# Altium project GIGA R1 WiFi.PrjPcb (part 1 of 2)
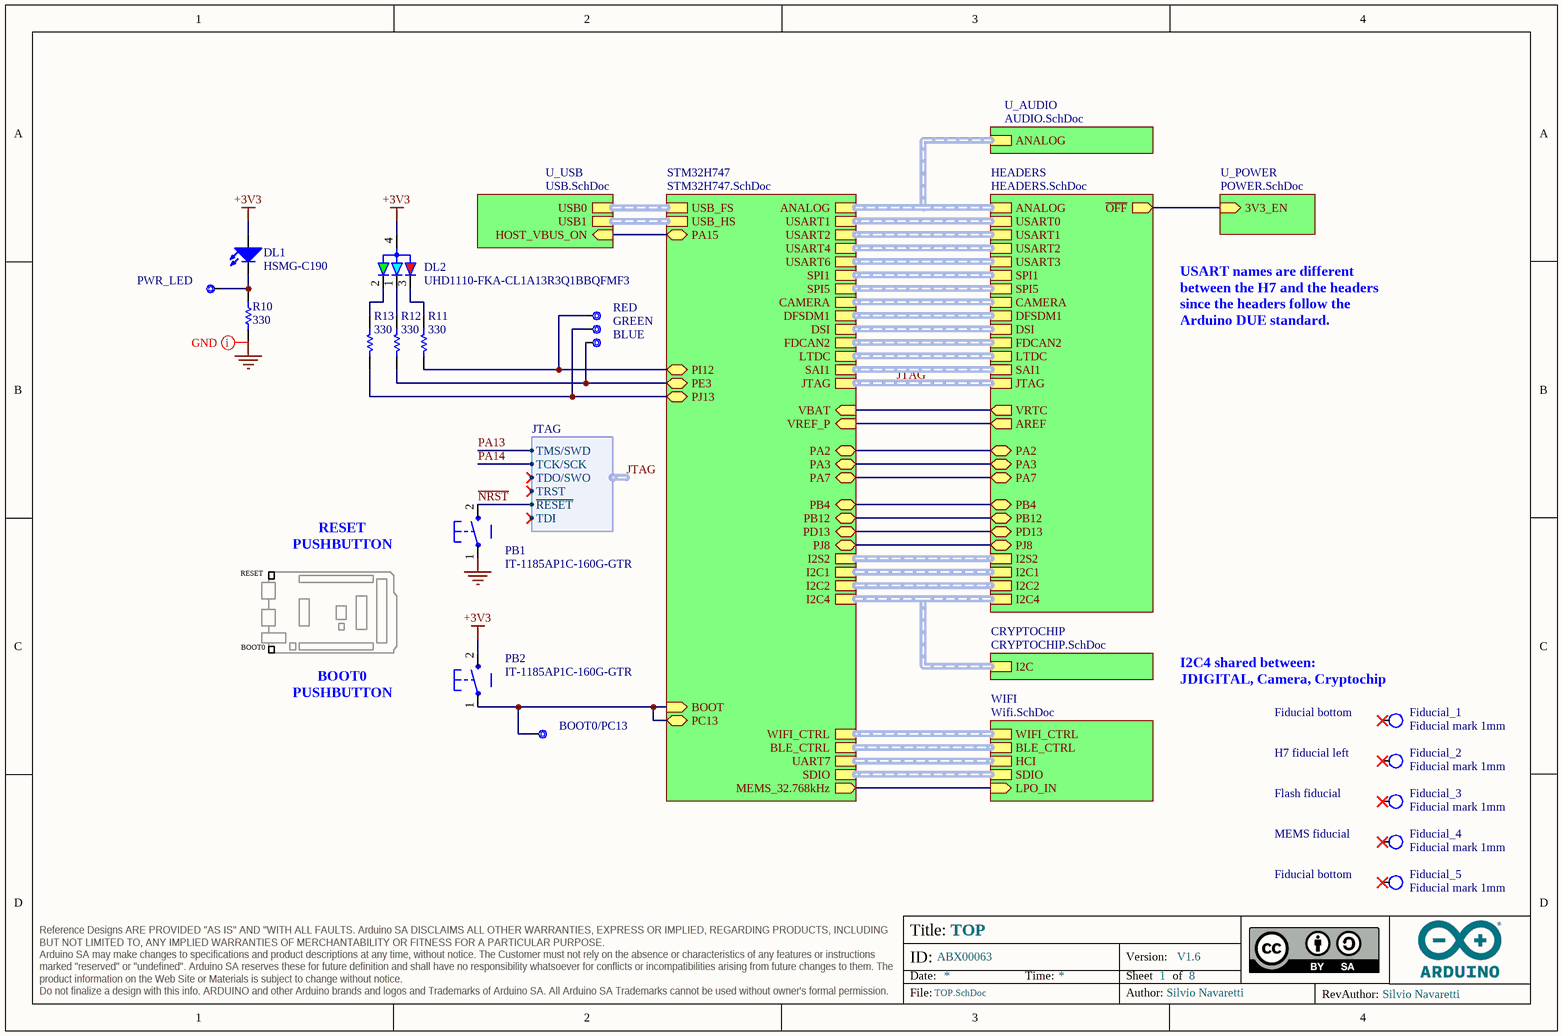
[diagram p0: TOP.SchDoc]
ADJUSTMENTS: _; BGA: X; BOARD_CODENAME: GIGA R1 WiFi; BOARD_INFO_AUTHOR: Silvio Navaretti; BOARD_INFO_AUTHOR_REV: Silvio Navaretti; DRILLS_BLIND: _; DRILLS_BURIED: _; DRILLS_COPPER_FILLING: _; DRILLS_FULL: X; DRILLS_LASER: _; DRILLS_PRESSFIT: _; DRILLS_RESIN_FILLING: _; DRILLS_SLOT: _; DRILLS_SOLDER_FILLING: X; EDGE_PLATING: _; ENIG: X; Er: _; FINISH_TBD: _; FLEX: _; FR4: X; FR4_HTG: _; HAL: _; HAL_LF: _; HOLE_TOP_BOTTOM: X; IPC1: _; IPC2: _; IPC3: _; IPCNA: _; MILLING: X; MIN_INSULATION_INNER: 0.127mm; MIN_INSULATION_OUTER: 0.127mm; MIN_TRACK_WIDTH_INNER: 0.127mm; MIN_TRACK_WIDTH_OUTER: 0.127mm; N_FIGURES: 6; NI/AU: _; NLAYERS: 6; PANEL_NO: _; PANEL_PROVIDED: X; PANEL_REQUESTED: _; PANEL_SIZE: 228mm x 179mm; PCB_SIZE: 101.6mm x 53.34mm; POLYMIDE: _; PRESSFIT: _; RIGID: X; RIGID/FLEX: _; SCORING: _; SILK_BOTTOM: X; SILK_COLOR: WHITE; SILK_TOP: X; SKU: ABX00063; SMD: X; SN/PB: _; SOLDERMASK_BOTTOM: X; SOLDERMASK_COLOR: BLUE; SOLDERMASK_PEELABLE_BOTTOM: _; SOLDERMASK_PEELABLE_COLOR: _; SOLDERMASK_PEELABLE_TOP: _; SOLDERMASK_TOP: X; TABS: _; TBD: _; THD: X; THICKNESS: 1.6mm; Version: V1.6
8 sheets, 228 parts. Net scope: hierarchical (ports join the sheet entries above them; power ports are global).
Board files: PCB.PcbDoc, PANEL.PcbDoc
Sheets:
  TOP.SchDoc
    U_AUDIO = AUDIO.SchDoc
    U_POWER = POWER.SchDoc
    U_USB = USB.SchDoc
    STM32H747 = STM32H747.SchDoc
    HEADERS = HEADERS.SchDoc
    WIFI = Wifi.SchDoc
    CRYPTOCHIP = CRYPTOCHIP.SchDoc

## Sheet TOP.SchDoc: TOP
size A4; Author: Silvio Navaretti; CompanyName: Arduino srl; DocumentNumber: ABX00063; Revision: V1.2; SheetNumber: 1; SheetTotal: 8; RevAuthor: Silvio Navaretti

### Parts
BLUE  CMP-018-0005-A.3  [TP-1.00MM]  (value not drawn)  (no BOM)
BOOT0/PC13  CMP-018-0005-A.3  [TP-1.00MM]  (value not drawn)  (no BOM)
DL1  HSMG-C190  [LEDC1608X80N-AK]
DL2  UHD1110-FKA-CL1A13R3Q1BBQFMF3  [UHD1110-FKA-CL1A13R3Q1BBQFMF3]
Fiducial_1  Fiducial mark 1mm  [Fiducial mark 1mm-Footprint-1]  (no BOM)
Fiducial_2  Fiducial mark 1mm  [Fiducial mark 1mm-Footprint-1]  (no BOM)
Fiducial_3  Fiducial mark 1mm  [Fiducial mark 1mm-Footprint-1]  (no BOM)
Fiducial_4  Fiducial mark 1mm  [Fiducial mark 1mm-Footprint-1]  (no BOM)
Fiducial_5  Fiducial mark 1mm  [Fiducial mark 1mm-Footprint-1]  (no BOM)
GREEN  CMP-018-0005-A.3  [TP-1.00MM]  (value not drawn)  (no BOM)
PB1  IT-1185AP1C-160G-GTR  [C&K_PTS820_NO_HOLES-1]
PB2  IT-1185AP1C-160G-GTR  [C&K_PTS820_NO_HOLES-1]
PWR_LED  CMP-018-0005-A.3  [TP-1.00MM]  (value not drawn)  (no BOM)
R10  value 330  [RES-0402]  (hidden comment: CRCW0402330RJNED)
R11  value 330  [RES-0402]  (hidden comment: CRCW0402330RJNED)
R12  value 330  [RES-0402]  (hidden comment: CRCW0402330RJNED)
R13  value 330  [RES-0402]  (hidden comment: CRCW0402330RJNED)
RED  CMP-018-0005-A.3  [TP-1.00MM]  (value not drawn)  (no BOM)

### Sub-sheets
CRYPTOCHIP = CRYPTOCHIP.SchDoc: I2C (harness I2C)
HEADERS = HEADERS.SchDoc: SPI5 (harness SPI), PB4 (bidir), I2C1 (harness I2C), LTDC (harness LTDC), SAI1 (harness SAI), I2C4 (harness I2C), USART0 (harness UART), USART3 (harness UART), USART2 (harness UART), USART1 (harness UART), I2C2 (harness I2C), PD13 (bidir), PA7 (bidir), PJ8 (bidir), PA2 (bidir), PA3 (bidir), ANALOG (harness ANALOG), FDCAN2 (harness FDCAN), I2S2 (harness I2S), DSI (harness DISPLAY), DFSDM1 (harness DFSDM), SPI1 (harness SPI), CAMERA (harness ARDUCAM), AREF (out), ~{OFF} (out), VRTC (out), JTAG (harness JTAG), PB12 (bidir)
STM32H747 = STM32H747.SchDoc: BOOT (in), DSI (harness DISPLAY), VREF_P (in), SDIO (harness SDC), USB_FS (harness USB), USB_HS (harness USB), PI12 (bidir), PE3 (bidir), PJ13 (bidir), UART7 (harness UART), PC13 (bidir), I2C1 (harness I2C), USART1 (harness UART), USART6 (harness UART), USART4 (harness UART), USART2 (harness UART), I2C2 (harness I2C), ANALOG (harness ANALOG), FDCAN2 (harness FDCAN), LTDC (harness LTDC), SAI1 (harness SAI), I2S2 (harness I2S), DFSDM1 (harness DFSDM), I2C4 (harness I2C), CAMERA (harness ARDUCAM), SPI5 (harness SPI), SPI1 (harness SPI), BLE_CTRL (harness BLE CTRL), WIFI_CTRL (harness WiFi CTRL), PD13 (bidir), PB4 (bidir), PA7 (bidir), PJ8 (bidir), PA2 (bidir), PA3 (bidir), JTAG (harness JTAG), PB12 (bidir), VBAT (in), MEMS_32.768kHz (out), PA15 (bidir)
U_AUDIO = AUDIO.SchDoc: ANALOG (harness ANALOG)
U_POWER = POWER.SchDoc: 3V3_EN (in)
U_USB = USB.SchDoc: USB0 (harness USB), USB1 (harness USB), HOST_VBUS_ON (in)
WIFI = Wifi.SchDoc: BLE_CTRL (harness BLE CTRL), HCI (harness UART), WIFI_CTRL (harness WiFi CTRL), SDIO (harness SDC), LPO_IN (in)

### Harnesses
JTAG: ~{RESET}, TCK/SCK, TDI, TDO/SWO, TMS/SWD, TRST

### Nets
+3V3: DL1.A DL2.4(ANODE) PB2.2
GND: PB1.1 R10.1
MEMS_32.768kHz: sheet STM32H747/MEMS_32.768kHz, sheet WIFI/LPO_IN
~{NRST}: PB1.2 ; sheet STM32H747/JTAG.~{RESET}  [project net JTAG.~{RESET}]
PA2: sheet STM32H747/PA2, sheet HEADERS/PA2
PA3: sheet STM32H747/PA3, sheet HEADERS/PA3
PA7: sheet STM32H747/PA7, sheet HEADERS/PA7
PA15: sheet U_USB/HOST_VBUS_ON, sheet STM32H747/PA15
PB4: sheet STM32H747/PB4, sheet HEADERS/PB4
PB12: sheet STM32H747/PB12, sheet HEADERS/PB12
PC13: BOOT0/PC13.X PB2.1 ; sheet STM32H747/BOOT, sheet STM32H747/PC13
PD13: sheet STM32H747/PD13, sheet HEADERS/PD13
PE3: BLUE.X R12.2 ; sheet STM32H747/PE3
PI12: R11.2 RED.X ; sheet STM32H747/PI12
PJ8: sheet STM32H747/PJ8, sheet HEADERS/PJ8
PJ13: GREEN.X R13.2 ; sheet STM32H747/PJ13
Net3V3_EN_X: sheet U_POWER/3V3_EN, sheet HEADERS/~{OFF}
NetDL1_C: DL1.C PWR_LED.X R10.2
NetDL2_1: DL2.1(BLUE_C) R12.1
NetDL2_2: DL2.2(GREEN_C) R13.1
NetDL2_3: DL2.3(RED_C) R11.1
NetJ1_3: sheet STM32H747/VBAT, sheet HEADERS/VRTC
NetJDIGITAL_3: sheet STM32H747/VREF_P, sheet HEADERS/AREF

Not connected (* = marked no-connect by the designer): Fiducial_1 1*; Fiducial_2 1*; Fiducial_3 1*; Fiducial_4 1*; Fiducial_5 1*

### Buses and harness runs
harness JTAG = sheet HEADERS/JTAG = sheet STM32H747/JTAG
harness sheet CRYPTOCHIP/I2C = sheet HEADERS/I2C4 = sheet STM32H747/I2C4
harness sheet HEADERS/ANALOG = sheet STM32H747/ANALOG = sheet U_AUDIO/ANALOG
harness sheet HEADERS/CAMERA = sheet STM32H747/CAMERA
harness sheet HEADERS/DFSDM1 = sheet STM32H747/DFSDM1
harness sheet HEADERS/DSI = sheet STM32H747/DSI
harness sheet HEADERS/FDCAN2 = sheet STM32H747/FDCAN2
harness sheet HEADERS/I2C1 = sheet STM32H747/I2C1
harness sheet HEADERS/I2C2 = sheet STM32H747/I2C2
harness sheet HEADERS/I2S2 = sheet STM32H747/I2S2
harness sheet HEADERS/LTDC = sheet STM32H747/LTDC
harness sheet HEADERS/SAI1 = sheet STM32H747/SAI1
harness sheet HEADERS/SPI1 = sheet STM32H747/SPI1
harness sheet HEADERS/SPI5 = sheet STM32H747/SPI5
harness sheet HEADERS/USART0 = sheet STM32H747/USART1
harness sheet HEADERS/USART1 = sheet STM32H747/USART2
harness sheet HEADERS/USART2 = sheet STM32H747/USART4
harness sheet HEADERS/USART3 = sheet STM32H747/USART6
harness sheet STM32H747/BLE_CTRL = sheet WIFI/BLE_CTRL
harness sheet STM32H747/SDIO = sheet WIFI/SDIO
harness sheet STM32H747/UART7 = sheet WIFI/HCI
harness sheet STM32H747/USB_FS = sheet U_USB/USB0
harness sheet STM32H747/USB_HS = sheet U_USB/USB1
harness sheet STM32H747/WIFI_CTRL = sheet WIFI/WIFI_CTRL

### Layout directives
net class GND: GND

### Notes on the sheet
- USART names are different between the H7 and the headers since the headers follow the Arduino DUE standard.
- RESET
- RESET
  PUSHBUTTON
- BOOT0
- BOOT0
  PUSHBUTTON
- (near Fiducial_1) I2C4 shared between:
  JDIGITAL, Camera, Cryptochip
- (near Fiducial_1) Fiducial bottom
- (near Fiducial_2) H7 fiducial left
- Flash fiducial
- MEMS fiducial
- Fiducial bottom

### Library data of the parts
BLUE BOOT0/PC13 GREEN PWR_LED RED = UT0013-A.4: Test point 1.00mm
DL1 = L0009-A.5: LED SMD 0603 GREEN/568 15mcd 120^; Manufacturer: Broadcom; Code Arduino: 2204
DL2 = L0026-A.4: LED RGB BLACK BODY SMD; Manufacturer: Cree LED; Code Arduino: L0026
Fiducial_1-Fiducial_5 = UT0023-A.6: Fiducial mark 1mm clearance 2mm
PB1 PB2 = B0001-A.7: PUSHBUTTON WHITE NO ANCHORS; Manufacturer: Switronic; Code Arduino: 0173
R10-R13 = R0017-A.23: RES CHIP 0402 330R 5% 1/16W; Manufacturer: Vishay; Power: 62.5mW; Code Arduino: 2229; Temperature coefficient: 200ppm

## Sheet AUDIO.SchDoc: AUDIO
size A4; Author: Silvio Navaretti; CompanyName: Arduino srl; DocumentNumber: ABX00063; Revision: V1.4; SheetNumber: 7; SheetTotal: 8; RevAuthor: Silvio Navaretti
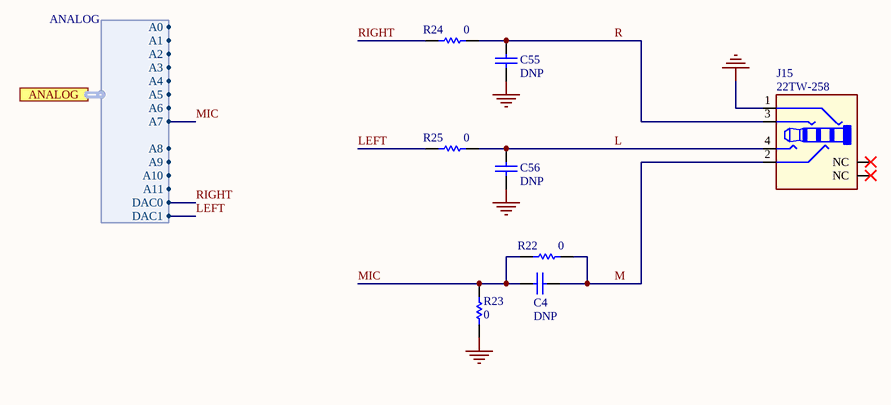
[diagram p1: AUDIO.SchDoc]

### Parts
C4  DNP CAP 0402  [CAP-0402]  (value not drawn)
C55  DNP CAP 0402  [CAP-0402]  (value not drawn)
C56  DNP CAP 0402  [CAP-0402]  (value not drawn)
J15  22TW-258  [22TW-258-Footprint-1]
R22  value 0  [RES-0402]  (hidden comment: CRCW04020000Z0EDC)
R23  value 0  [RES-0402]  (hidden comment: CRCW04020000Z0EDC)
R24  value 0  [RES-0402]  (hidden comment: CRCW04020000Z0EDC)
R25  value 0  [RES-0402]  (hidden comment: CRCW04020000Z0EDC)

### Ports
ANALOG (harness ANALOG)

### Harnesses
ANALOG: A0, A1, A2, A3, A7, A6, A5, A4, A8, A9, A10, A11, DAC0, DAC1

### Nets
GND: C55.1 C56.1 J15.1 R23.1
L: C56.2 J15.4 R25.2  [project net L_7]
LEFT: R25.1 ; port ANALOG.DAC1
M: C4.1 J15.2 R22.2  [project net M_7]
MIC: C4.2 R22.1 R23.2 ; port ANALOG.A7
R: C55.2 J15.3 R24.2  [project net R_7]
RIGHT: R24.1 ; port ANALOG.DAC0  [project net PA4]

Not connected (* = marked no-connect by the designer): J15 NC1(NC)* NC2(NC)*

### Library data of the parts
C4 C55 C56 = C0095-A.6: Code Arduino: C0095
J15 = J0273-A.8: Conn Jack 4 POLES 3.5mm SMD; Manufacturer: 4UCONN; Code Arduino: J0273
R22-R25 = R0000-A.23: RES CHIP 0402 0R 1/16W; Manufacturer: Vishay; Power: 62.5mW; Tolerance: 0%; Code Arduino: 0039; Temperature coefficient: 0ppm

## Sheet POWER.SchDoc: POWER
size A4; Author: Silvio Navaretti; CompanyName: Arduino srl; DocumentNumber: ABX00063; Revision: V1.4; SheetNumber: 4; SheetTotal: 8; RevAuthor: Silvio Navaretti
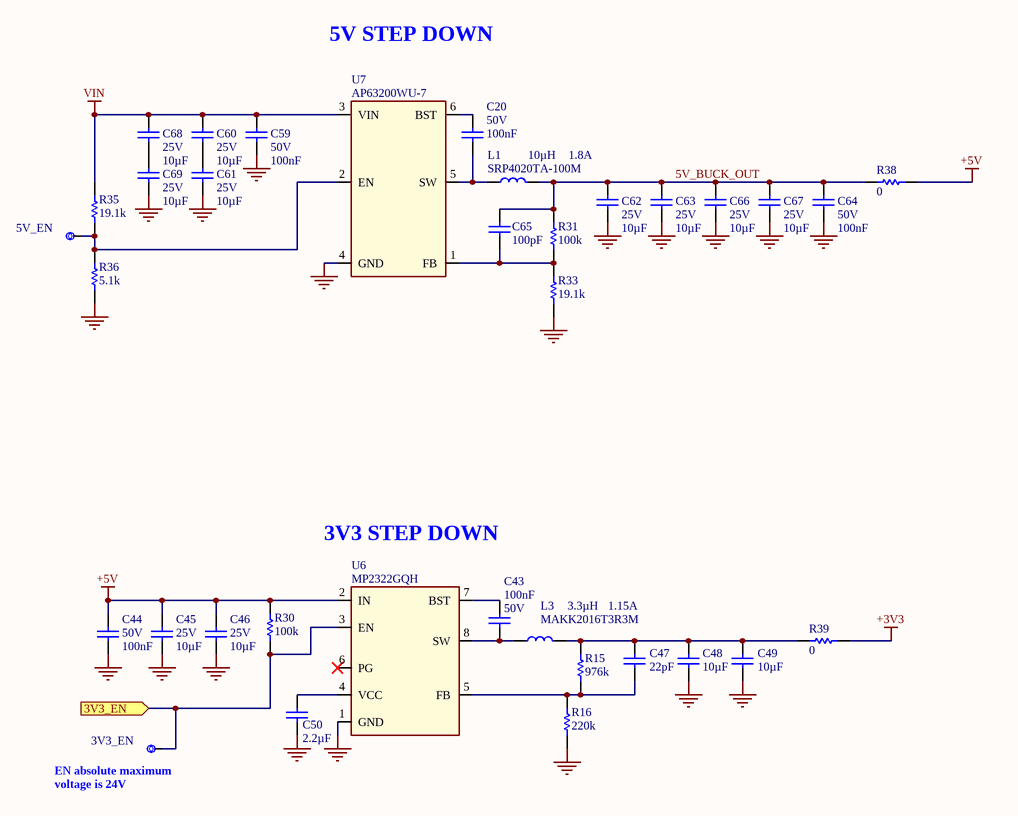
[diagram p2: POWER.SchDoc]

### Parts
3V3_EN  CMP-018-0005-A.3  [TP-1.00MM]  (value not drawn)  (no BOM)
5V_EN  CMP-018-0005-A.3  [TP-1.00MM]  (value not drawn)  (no BOM)
C20  value 100nF  Voltage: 50V  [CAP-0402]  (hidden comment: GRM155R61H104KE19D)
C43  value 100nF  Voltage: 50V  [CAP-0402]  (hidden comment: GRM155R61H104KE19D)
C44  value 100nF  Voltage: 50V  [CAP-0402]  (hidden comment: GRM155R61H104KE19D)
C45  value 10µF  Voltage: 25V  [CAP-0603]  (hidden comment: C1608A106M250NT)
C46  value 10µF  Voltage: 25V  [CAP-0603]  (hidden comment: C1608A106M250NT)
C47  value 22pF  [CAP-0402]  (hidden comment: 0402N220J500CT)
C48  value 10µF  [CAP-0603]  (hidden comment: C1608A106M250NT)
C49  value 10µF  [CAP-0603]  (hidden comment: C1608A106M250NT)
C50  value 2.2µF  [CAP-0402]  (hidden comment: GRM155R60J225KE95D)
C59  value 100nF  Voltage: 50V  [CAP-0402]  (hidden comment: GRM155R61H104KE19D)
C60  value 10µF  Voltage: 25V  [CAP-0603]  (hidden comment: C1608A106M250NT)
C61  value 10µF  Voltage: 25V  [CAP-0603]  (hidden comment: C1608A106M250NT)
C62  value 10µF  Voltage: 25V  [CAP-0603]  (hidden comment: C1608A106M250NT)
C63  value 10µF  Voltage: 25V  [CAP-0603]  (hidden comment: C1608A106M250NT)
C64  value 100nF  Voltage: 50V  [CAP-0402]  (hidden comment: GRM155R61H104KE19D)
C65  value 100pF  [CAP-0402]  (hidden comment: CC0402JRNPO9BN101)
C66  value 10µF  Voltage: 25V  [CAP-0603]  (hidden comment: C1608A106M250NT)
C67  value 10µF  Voltage: 25V  [CAP-0603]  (hidden comment: C1608A106M250NT)
C68  value 10µF  Voltage: 25V  [CAP-0603]  (hidden comment: C1608A106M250NT)
C69  value 10µF  Voltage: 25V  [CAP-0603]  (hidden comment: C1608A106M250NT)
L1  SRP4020TA-100M  Inductance: 10µH  Current: 1.8A  [SRP4020]
L3  MAKK2016T3R3M  Max DC Current: 1.15A  Inductance: 3.3µH  [MAKK2016T3R3M-Footprint-1]
R15  value 976k  [RES-0402]  (hidden comment: CRCW0402976KFKED)
R16  value 220k  [RES-0402]  (hidden comment: CRCW0402220KFKED)
R30  value 100k  [RES-0402]  (hidden comment: CRCW0402100KFKEDC)
R31  value 100k  [RES-0402]  (hidden comment: CRCW0402100KFKEDC)
R33  value 19.1k  [RES-0402]  (hidden comment: CRCW040219K1FKEDC)
R35  value 19.1k  [RES-0402]  (hidden comment: CRCW040219K1FKEDC)
R36  value 5.1k  [RES-0402]  (hidden comment: RC0402FR-075K1L)
R38  value 0  [RES-0402]  (hidden comment: CRCW04020000Z0EDC)
R39  value 0  [RES-0402]  (hidden comment: CRCW04020000Z0EDC)
U6  MP2322GQH  [QFN50P150X200X90-8L]
U7  AP63200WU-7  [SOT95P280X100-6N]

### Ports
3V3_EN (in)

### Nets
+3V3: R39.2
+5V: C44.1 C45.2 C46.2 R30.1 R38.2 U6.2(IN)
GND: C44.2 C45.1 C46.1 C48.1 C49.1 C50.1 C59.2 C61.1 C62.1 C63.1 C64.2 C66.1 C67.1 C69.1 R16.1 R33.1 R36.2 U6.1(GND) U7.4(GND)
VIN: C59.1 C60.2 C68.2 R35.1 U7.3(VIN)
5V_BUCK_OUT: C62.2 C63.2 C64.1 C65.2 C66.2 C67.2 L1.2 R31.1 R38.1  [project net 5V_BUCK_OUT_4]
Net3V3_EN_X: 3V3_EN.X R30.2 U6.3(EN) ; port 3V3_EN
Net5V_EN_X: 5V_EN.X R35.2 R36.1 U7.2(EN)
NetC20_1: C20.1 U7.6(BST)
NetC20_2: C20.2 L1.1 U7.5(SW)
NetC43_1: C43.1 L3.1 U6.8(SW)
NetC43_2: C43.2 U6.7(BST)
NetC47_1: C47.1 R15.1 R16.2 U6.5(FB)
NetC47_2: C47.2 C48.2 C49.2 L3.2 R15.2 R39.1
NetC50_2: C50.2 U6.4(VCC)
NetC60_1: C60.1 C61.2
NetC65_1: C65.1 R31.2 R33.2 U7.1(FB)
NetC68_1: C68.1 C69.2

Not connected (* = marked no-connect by the designer): U6 6(PG)*

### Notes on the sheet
- 5V STEP DOWN
- 3V3 STEP DOWN
- (near 3V3_EN) EN absolute maximum voltage is 24V

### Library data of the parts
3V3_EN 5V_EN = UT0013-A.4: Test point 1.00mm
C20 C43 C44 C59 C64 = C0015-A.14: CAP CHIP 0402 100nF 10% 50V X5R; Manufacturer: Murata; Code Arduino: A5141
C45 C46 C48 C49 C60-C63 C66-C69 = C0047-A.18: CAP CHIP 0603 10uF 20% 25V X5R; Manufacturer: Hottech; Code Arduino: 2213
C47 = C0029-A.14: CAP CHIP 0402 22pF 5% 50V C0G; Manufacturer: Walsin; Code Arduino: 0137
C50 = C0031-A.14: CAP CHIP 0402 2.2uF 10% 6.3V X5R; Manufacturer: Murata; Code Arduino: A5529
C65 = C0013-A.4: CAP CHIP 0402 100pF 10% 50V C0G; Manufacturer: Yageo; Code Arduino: C0013; Tolerance: 5%
L1 = I0065-A.2: IND FIXED 10UH IRMS 1.8A ISAT 2.3A 243m ohm SMD 4.45x4mm; Manufacturer: Bourns; Value: 10u; Code Arduino: I0065
L3 = I0045-A.10: IND CHIP 0806 3.3 uH 20% 1.2A; Manufacturer: Taiyo Yuden; Core Material: Metal; DC Resistance (DCR): 255mR; Code Arduino: I0045; Test Frequency: 2MHz; Shielding: Shielded; Value: 3.3µH
R15 = R0070-A.24: RES CHIP 0402 976k 1% 1/16W; Manufacturer: Vishay; Power: 62.5mW; Code Arduino: R0070; Temperature coefficient: 100ppm
R16 = R0028-A.23: RES CHIP 0402 220k 1% 1/16W; Manufacturer: Vishay; Code Arduino: 2334; Power: 62.5mW; Temperature coefficient: 200ppm
R30 R31 = R0001-A.23: RES CHIP 0402 100k 1% 1/16W; Manufacturer: Vishay; Power: 62.5mW; Code Arduino: 0134; Temperature coefficient: 100ppm
R33 = R0033-A.23: RES CHIP 0402 19k1 1% 1/16W; Manufacturer: Vishay; Code Arduino: A5369; Power: 62.5mW; Temperature coefficient: 100ppm
R35 = R0033-A.23: RES CHIP 0402 19k1 1% 1/16W; Manufacturer: Vishay; Power: 62.5mW; Code Arduino: A5369; Temperature coefficient: 100ppm
R36 = R0210-A.18: RES CHIP 0402 5k1 1% 1/16W; Manufacturer: YAGEO; Power: 63mW; Code Arduino: R0210; Temperature coefficient: 100ppm
R38 R39 = R0000-A.23: as R22 on sheet AUDIO
U6 = U0072-A.8: IC STEP DOWN CONV 1A 22V QFN8; Manufacturer: Monolithic Power Systems; Code Arduino: U0072
U7 = U0241-A.6: IC BUCK VIN 3V8 to 32V Iout 4A duty 100% fsw 500kHz TSOT26; Manufacturer: Diodes Incorporated; Code Arduino: U0241

## Sheet USB.SchDoc: USB
size A4; Author: Silvio Navaretti; CompanyName: Arduino srl; DocumentNumber: ABX00063; Revision: V1.4; SheetNumber: 3; SheetTotal: 8; RevAuthor: Silvio Navaretti
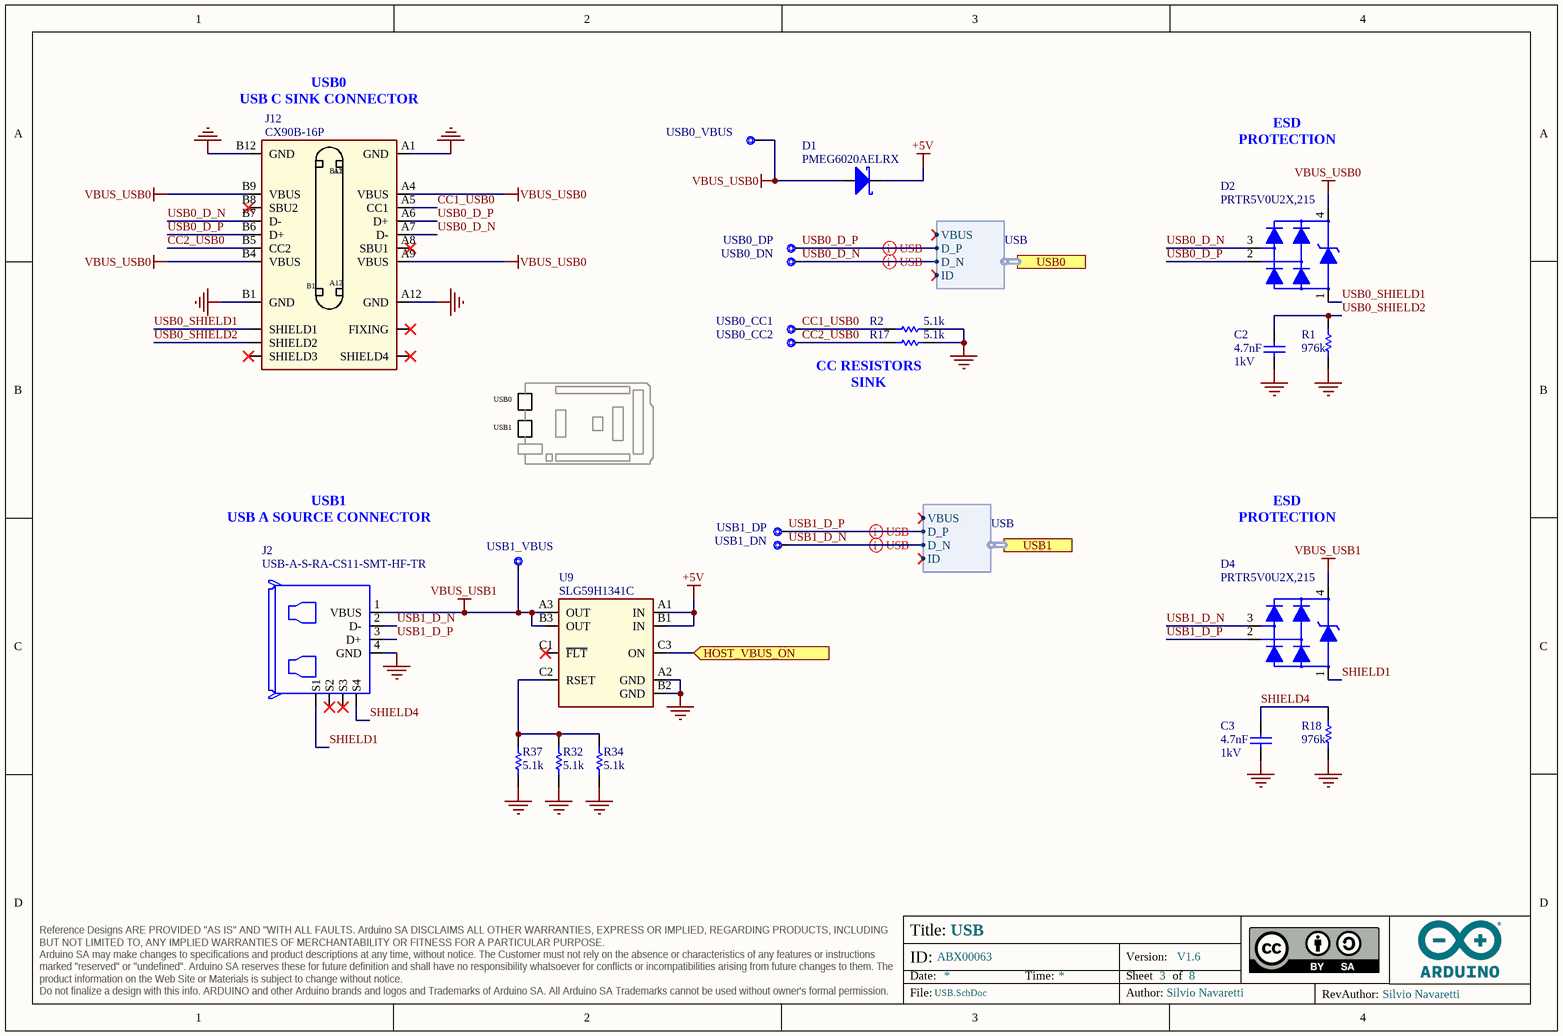
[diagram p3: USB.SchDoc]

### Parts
C2  value 4.7nF  Voltage: 1kV  [CAP-0805]  (hidden comment: FV21X472K102ECG)
C3  value 4.7nF  Voltage: 1kV  [CAP-0805]  (hidden comment: FV21X472K102ECG)
D1  PMEG6020AELRX  [SOD123-1]
D2  PRTR5V0U2X,215  [SOT190P230X110-4N]
D4  PRTR5V0U2X,215  [SOT190P230X110-4N]
J2  USB-A-S-RA-CS11-SMT-HF-TR  [USB-A-S-RA-CS11-SMT-HF-TR]
J12  CX90B-16P  [CX90B-16P-Footprint-1]
R1  value 976k  [RES-0402]  (hidden comment: CRCW0402976KFKED)
R2  value 5.1k  [RES-0402]  (hidden comment: RC0402FR-075K1L)
R17  value 5.1k  [RES-0402]  (hidden comment: RC0402FR-075K1L)
R18  value 976k  [RES-0402]  (hidden comment: CRCW0402976KFKED)
R32  value 5.1k  [RES-0402]  (hidden comment: RC0402FR-075K1L)
R34  value 5.1k  [RES-0402]  (hidden comment: RC0402FR-075K1L)
R37  value 5.1k  [RES-0402]  (hidden comment: RC0402FR-075K1L)
U9  SLG59H1341C  [BGA9C40P3X3_121X121X62]
USB0_CC1  CMP-018-0005-A.3  [TP-1.00MM]  (value not drawn)  (no BOM)
USB0_CC2  CMP-018-0005-A.3  [TP-1.00MM]  (value not drawn)  (no BOM)
USB0_DN  CMP-018-0005-A.3  [TP-1.00MM]  (value not drawn)  (no BOM)
USB0_DP  CMP-018-0005-A.3  [TP-1.00MM]  (value not drawn)  (no BOM)
USB0_VBUS  CMP-018-0005-A.3  [TP-1.00MM]  (value not drawn)  (no BOM)
USB1_DN  CMP-018-0005-A.3  [TP-1.00MM]  (value not drawn)  (no BOM)
USB1_DP  CMP-018-0005-A.3  [TP-1.00MM]  (value not drawn)  (no BOM)
USB1_VBUS  CMP-018-0005-A.3  [TP-1.00MM]  (value not drawn)  (no BOM)

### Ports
HOST_VBUS_ON (in), USB0 (harness USB), USB1 (harness USB)

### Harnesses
USB: VBUS, D_P, D_N, ID

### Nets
+5V: D1.C U9.A1(IN) U9.B1(IN)
GND: C2.1 C3.1 J2.4(GND) J12.A1(GND) J12.A12(GND) J12.B1(GND) J12.B12(GND) R1.1 R2.2 R17.2 R18.1 R32.1 R34.1 R37.1 U9.A2(GND) U9.B2(GND)
VBUS_USB0: D1.A D2.4 J12.A4(VBUS) J12.A9(VBUS) J12.B4(VBUS) J12.B9(VBUS) USB0_VBUS.X
VBUS_USB1: D4.4 J2.1(VBUS) U9.A3(OUT) U9.B3(OUT) USB1_VBUS.X
CC1_USB0: J12.A5(CC1) R2.1 USB0_CC1.X  [project net CC1_USB0_3]
CC2_USB0: J12.B5(CC2) R17.1 USB0_CC2.X  [project net CC2_USB0_3]
PA15: U9.C3(ON) ; port HOST_VBUS_ON
SHIELD1: D4.1 J2.SHIELD1(S1)  [project net SHIELD1_3]
SHIELD4: C3.2 J2.SHIELD4(S4) R18.2  [project net SHIELD4_3]
USB0_D_N: D2.3 J12.A7(D-) J12.B7(D-) USB0_DN.X ; port USB0.D_N
USB0_D_P: D2.2 J12.A6(D+) J12.B6(D+) USB0_DP.X ; port USB0.D_P
USB0_SHIELD1: D2.1 J12.SHIELD1  [project net USB0_SHIELD1_3]
USB0_SHIELD2: C2.2 J12.SHIELD2 R1.2  [project net USB0_SHIELD2_3]
USB1_D_N: D4.3 J2.2(D-) USB1_DN.X ; port USB1.D_N
USB1_D_P: D4.2 J2.3(D+) USB1_DP.X ; port USB1.D_P
NetR32_2: R32.2 R34.2 R37.2 U9.C2(RSET)

Not connected (* = marked no-connect by the designer): J2 SHIELD2(S2)* SHIELD3(S3)*; J12 A8(SBU1)* B8(SBU2)* FIXING* SHIELD3* SHIELD4*; U9 C1(~{FLT})*

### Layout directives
differential pair; differential pair class USB: USB0_D_N, USB0_D_P, USB1_D_N, USB1_D_P

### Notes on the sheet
- (near J12) USB0
  USB C SINK CONNECTOR
- ESD PROTECTION
- USB0
- USB1
- CC RESISTORS
  SINK
- USB1
  USB A SOURCE CONNECTOR

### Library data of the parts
C2 C3 = C0059-A.14: CAP CHIP 0805 4.7nF 10% 1000V X7R; Manufacturer: PSA Shenzen; Code Arduino: 0689
D1 = D0026-A.6: DIODE SCHOTTKY SMD 2A 60V SOD123FL; Manufacturer: Nexperia; Manucturer Part Number 2: SS26L; Code Arduino: 2208; Forward Voltage: 0.6V; Manucturer 2: Hottech
D2 D4 = D0025-A.5: TVS ARRAY 4LIN.8kV 1pF SOT143B; Manufacturer: Nexperia; Device Type: ESD protection; Code Arduino: 2209
J2 = J0329-A.9: CONN USB A 2.0 FEMALE RIGHT ANGLE SMD + TH TAPE AND REEL; Manufacturer: Adam Tech; Code Arduino: J0329
J12 = J0272-A.3: CONN RCPT USB3.1 TYPEC 16POS SMD; Manufacturer: Hirose; Code Arduino: J0272
R1 R18 = R0070-A.24: as R15 on sheet POWER
R2 R17 R32 R34 R37 = R0210-A.18: RES CHIP 0402 5k1 1% 1/16W; Manufacturer: YAGEO; Code Arduino: R0210; Power: 63mW; Temperature coefficient: 100ppm
U9 = U0272-A.3: IC Power switch 2.5V to 5.5V 1A reverse blocking, adj current limit, WLCSP9; Manufacturer: Renesas; Code Arduino: U0272
USB0_CC1 USB0_CC2 USB0_DN USB0_DP USB0_VBUS USB1_DN USB1_DP USB1_VBUS = UT0013-A.4: Test point 1.00mm

## Sheet STM32H747.SchDoc: STM32H747
size A3; Author: Silvio Navaretti; CompanyName: Arduino srl; DocumentNumber: ABX00063; Revision: V1.4; SheetNumber: 5; SheetTotal: 8; RevAuthor: Silvio Navaretti
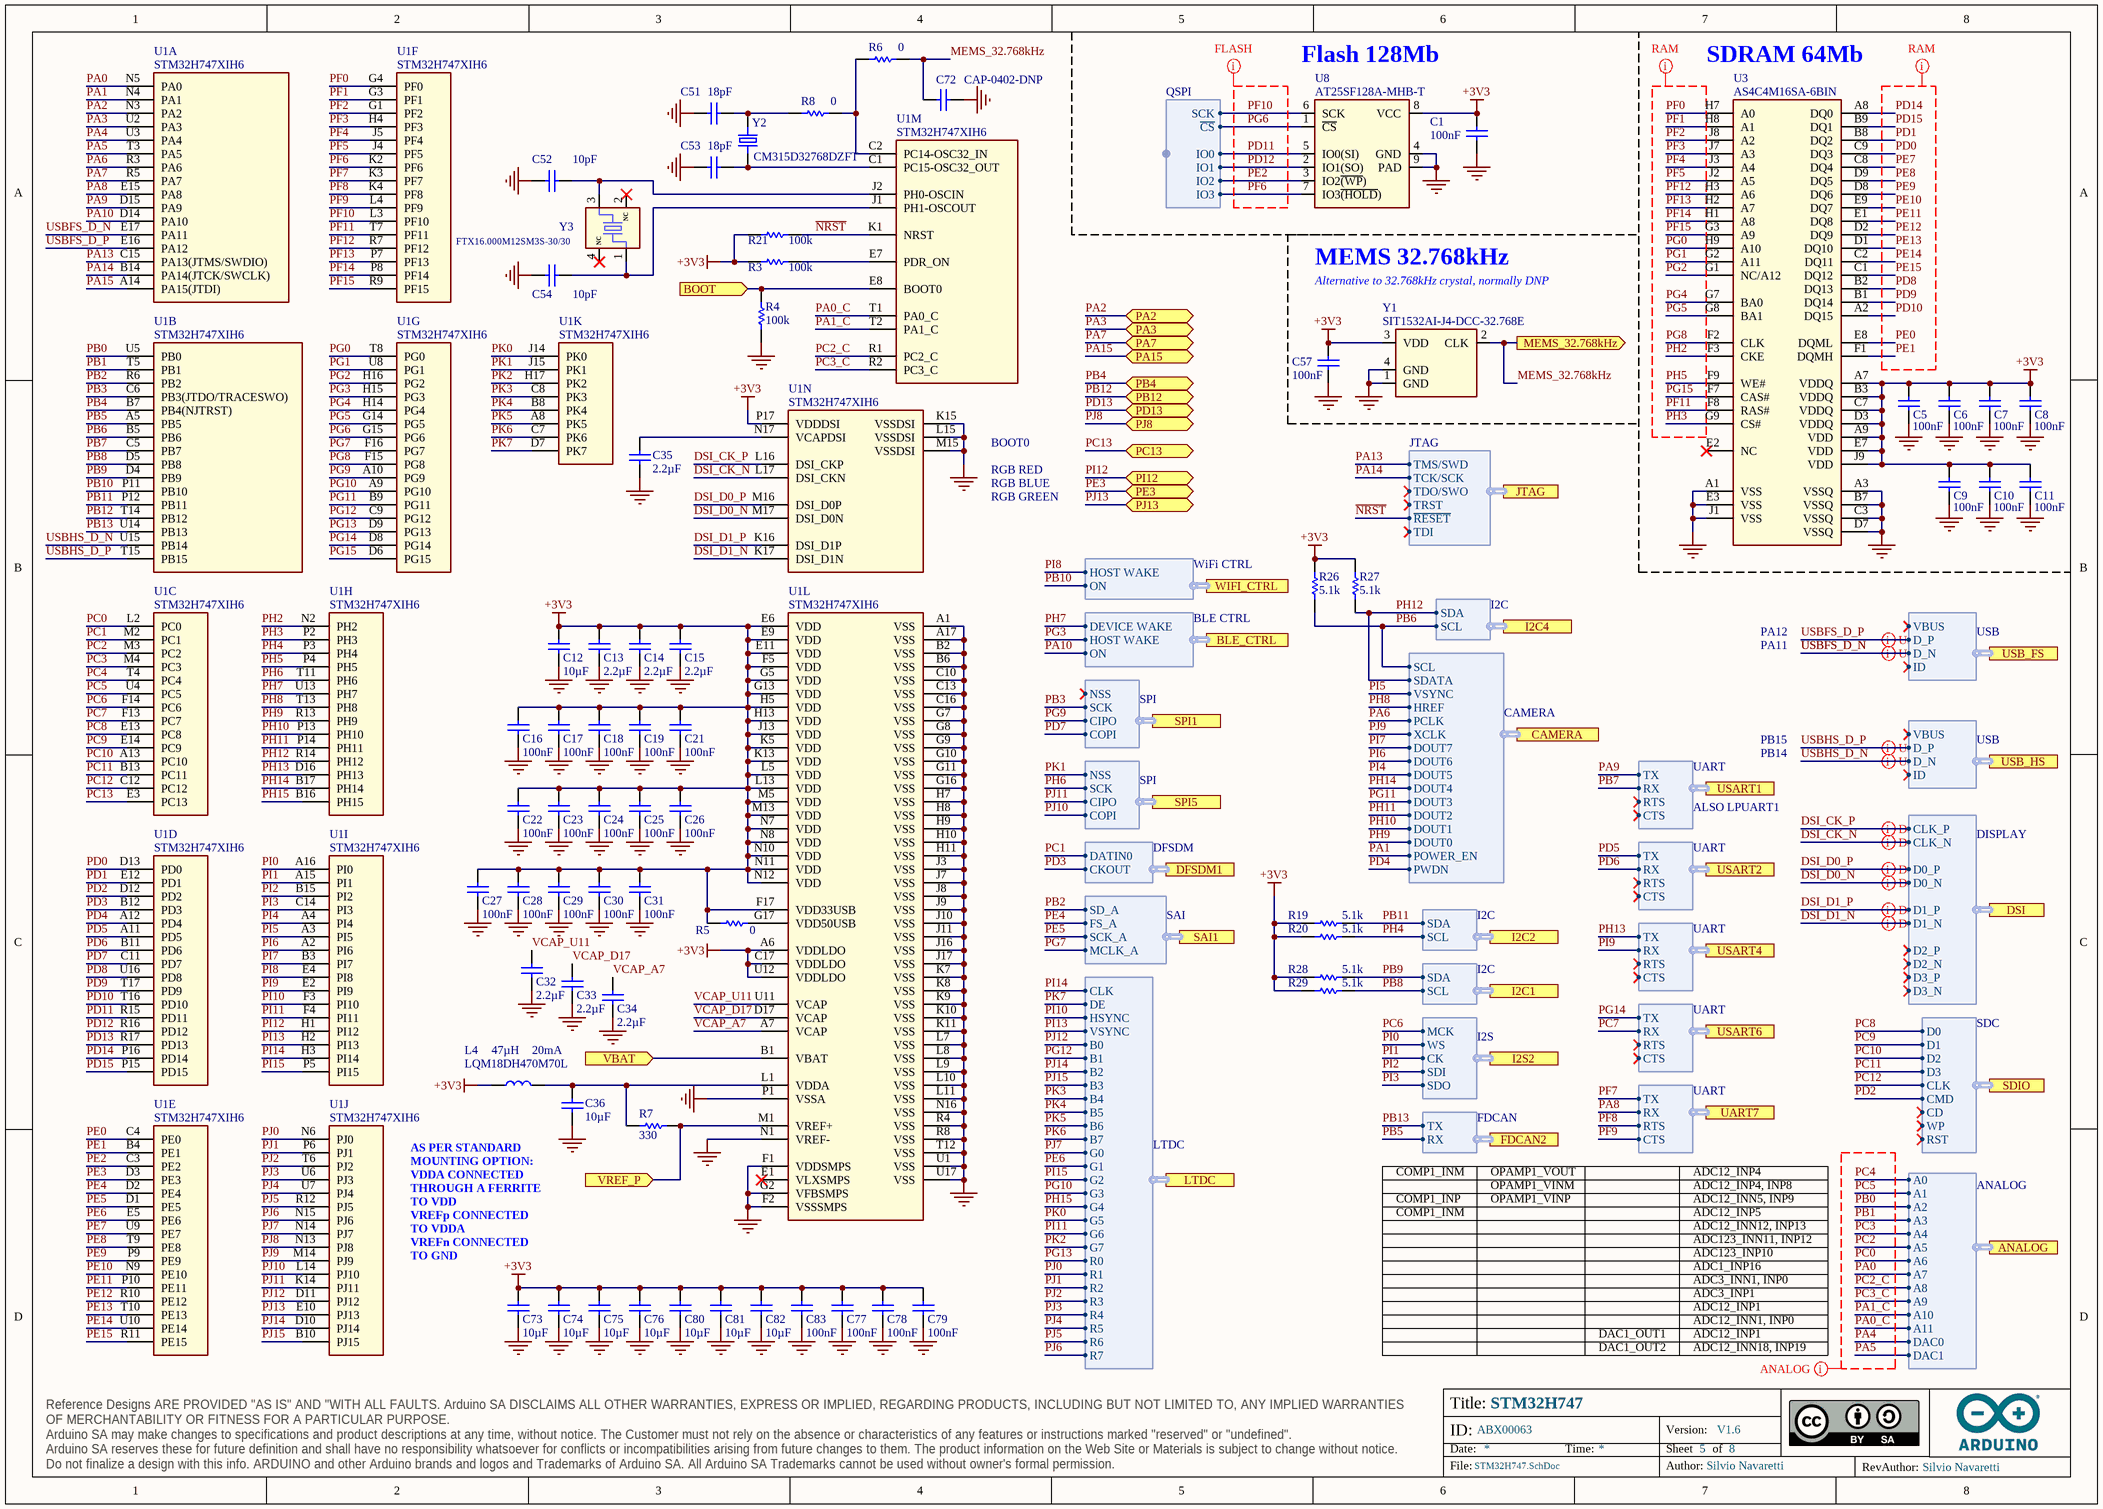
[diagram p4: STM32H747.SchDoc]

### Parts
C1  value 100nF  [CAP-0402]  (hidden comment: GRM155R61H104KE19D)
C5  value 100nF  [CAP-0402]  (hidden comment: GRM155R61H104KE19D)
C6  value 100nF  [CAP-0402]  (hidden comment: GRM155R61H104KE19D)
C7  value 100nF  [CAP-0402]  (hidden comment: GRM155R61H104KE19D)
C8  value 100nF  [CAP-0402]  (hidden comment: GRM155R61H104KE19D)
C9  value 100nF  [CAP-0402]  (hidden comment: GRM155R61H104KE19D)
C10  value 100nF  [CAP-0402]  (hidden comment: GRM155R61H104KE19D)
C11  value 100nF  [CAP-0402]  (hidden comment: GRM155R61H104KE19D)
C12  value 10µF  [CAP-0402]  (hidden comment: GRM155R60J106ME05D)
C13  value 2.2µF  [CAP-0402]  (hidden comment: GRM155R60J225KE95D)
C14  value 2.2µF  [CAP-0402]  (hidden comment: GRM155R60J225KE95D)
C15  value 2.2µF  [CAP-0402]  (hidden comment: GRM155R60J225KE95D)
C16  value 100nF  [CAP-0402]  (hidden comment: GRM155R61H104KE19D)
C17  value 100nF  [CAP-0402]  (hidden comment: GRM155R61H104KE19D)
C18  value 100nF  [CAP-0402]  (hidden comment: GRM155R61H104KE19D)
C19  value 100nF  [CAP-0402]  (hidden comment: GRM155R61H104KE19D)
C21  value 100nF  [CAP-0402]  (hidden comment: GRM155R61H104KE19D)
C22  value 100nF  [CAP-0402]  (hidden comment: GRM155R61H104KE19D)
C23  value 100nF  [CAP-0402]  (hidden comment: GRM155R61H104KE19D)
C24  value 100nF  [CAP-0402]  (hidden comment: GRM155R61H104KE19D)
C25  value 100nF  [CAP-0402]  (hidden comment: GRM155R61H104KE19D)
C26  value 100nF  [CAP-0402]  (hidden comment: GRM155R61H104KE19D)
C27  value 100nF  [CAP-0402]  (hidden comment: GRM155R61H104KE19D)
C28  value 100nF  [CAP-0402]  (hidden comment: GRM155R61H104KE19D)
C29  value 100nF  [CAP-0402]  (hidden comment: GRM155R61H104KE19D)
C30  value 100nF  [CAP-0402]  (hidden comment: GRM155R61H104KE19D)
C31  value 100nF  [CAP-0402]  (hidden comment: GRM155R61H104KE19D)
C32  value 2.2µF  [CAP-0402]  (hidden comment: GRM155R60J225KE95D)
C33  value 2.2µF  [CAP-0402]  (hidden comment: GRM155R60J225KE95D)
C34  value 2.2µF  [CAP-0402]  (hidden comment: GRM155R60J225KE95D)
C35  value 2.2µF  [CAP-0402]  (hidden comment: GRM155R60J225KE95D)
C36  value 10µF  [CAP-0402]  (hidden comment: GRM155R60J106ME05D)
C51  value 18pF  [CAP-0402]  (hidden comment: C0402C180J5GACTU)
C52  value 10pF  [CAP-0402]  (hidden comment: C0402H100J5GACTU)
C53  value 18pF  [CAP-0402]  (hidden comment: C0402C180J5GACTU)
C54  value 10pF  [CAP-0402]  (hidden comment: C0402H100J5GACTU)
C57  value 100nF  [CAP-0402]  (hidden comment: GRM155R61H104KE19D)
C72  CAP-0402-DNP  [CAP-0402]
C73  value 10µF  [CAP-0402]  (hidden comment: GRM155R60J106ME05D)
C74  value 10µF  [CAP-0402]  (hidden comment: GRM155R60J106ME05D)
C75  value 10µF  [CAP-0402]  (hidden comment: GRM155R60J106ME05D)
C76  value 10µF  [CAP-0402]  (hidden comment: GRM155R60J106ME05D)
C77  value 100nF  [CAP-0402]  (hidden comment: GRM155R61H104KE19D)
C78  value 100nF  [CAP-0402]  (hidden comment: GRM155R61H104KE19D)
C79  value 100nF  [CAP-0402]  (hidden comment: GRM155R61H104KE19D)
C80  value 10µF  [CAP-0402]  (hidden comment: GRM155R60J106ME05D)
C81  value 10µF  [CAP-0402]  (hidden comment: GRM155R60J106ME05D)
C82  value 10µF  [CAP-0402]  (hidden comment: GRM155R60J106ME05D)
C83  value 100nF  [CAP-0402]  (hidden comment: GRM155R61H104KE19D)
L4  LQM18DH470M70L  Current: 20mA  Inductance: 47µH  [L-0603]
R3  value 100k  [RES-0402]  (hidden comment: CRCW0402100KFKEDC)
R4  value 100k  [RES-0402]  (hidden comment: CRCW0402100KFKEDC)
R5  value 0  [RES-0402]  (hidden comment: CRCW04020000Z0EDC)
R6  value 0  [RES-0402]  (hidden comment: CRCW04020000Z0EDC)
R7  value 330  [RES-0402]  (hidden comment: CRCW0402330RJNED)
R8  value 0  [RES-0402]  (hidden comment: CRCW04020000Z0EDC)
R19  value 5.1k  [RES-0402]  (hidden comment: RC0402FR-075K1L)
R20  value 5.1k  [RES-0402]  (hidden comment: RC0402FR-075K1L)
R21  value 100k  [RES-0402]  (hidden comment: CRCW0402100KFKEDC)
R26  value 5.1k  [RES-0402]  (hidden comment: RC0402FR-075K1L)
R27  value 5.1k  [RES-0402]  (hidden comment: RC0402FR-075K1L)
R28  value 5.1k  [RES-0402]  (hidden comment: RC0402FR-075K1L)
R29  value 5.1k  [RES-0402]  (hidden comment: RC0402FR-075K1L)
U1  STM32H747XIH6  [STM32H747XIH6-Footprint-1]  (parts A,B,C,D,E,F,G,H,I,J,K,L,M,N of 14)
U3  AS4C4M16SA-6BIN  [AS4C4M16SA-7BCN-Footprint-1]
U8  AT25SF128A-MHB-T  [PSON127P600X60_HS-9N]
Y1  SIT1532AI-J4-DCC-32.768E  [SiT1532AI-J4-DCC-32.768E-Footprint-1]
Y2  CM315D32768DZFT  [ABS07]
Y3  FTX16.000M12SM3S-30/30  [CRYSTAL_3.2x2.5mm_16MHz]

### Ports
ANALOG (harness ANALOG), BLE_CTRL (harness BLE CTRL), BOOT (in), CAMERA (harness CAMERA), DFSDM1 (harness DFSDM), DSI (harness DISPLAY), FDCAN2 (harness FDCAN), I2C1 (harness I2C), I2C2 (harness I2C), I2C4 (harness I2C), I2S2 (harness I2S), JTAG (harness JTAG), LTDC (harness LTDC), MEMS_32.768kHz (out), PA2 (bidir), PA3 (bidir), PA7 (bidir), PA15 (bidir), PB4 (bidir), PB12 (bidir), PC13 (bidir), PD13 (bidir), PE3 (bidir), PI12 (bidir), PJ8 (bidir), PJ13 (bidir), SAI1 (harness SAI), SDIO (harness SDC), SPI1 (harness SPI), SPI5 (harness SPI), UART7 (harness UART), USART1 (harness UART), USART2 (harness UART), USART4 (harness UART), USART6 (harness UART), USB_FS (harness USB), USB_HS (harness USB), VBAT (in), VREF_P (in), WIFI_CTRL (harness WiFi CTRL)

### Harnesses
DISPLAY: CLK_N, CLK_P, D0_N, D0_P, D1_N, D1_P, D2_N, D2_P, D3_N, D3_P
SDC: CLK, CMD, D0, D1, D2, D3, CD, WP, RST
USB: VBUS, D_P, D_N, ID
UART: RX, TX, RTS, CTS
I2C: SDA, SCL
ANALOG: A0, A1, A2, A3, A7, A6, A5, A4, A8, A9, A10, A11, DAC0, DAC1
FDCAN: RX, TX
LTDC: B0, B1, B2, B3, B4, B5, B6, B7, CLK, DE, G0, G1, G2, G3, G4, G5, G6, G7, HSYNC, R0, R1, R2, R3, R4, R5, R6, R7, VSYNC
SAI: SD_A, FS_A, SCK_A, MCLK_A
I2S: CK, SDI, SDO, WS, MCK
DFSDM: DATIN0, CKOUT
CAMERA: SCL, SDATA, VSYNC, HREF, PCLK, XCLK, DOUT7, DOUT6, DOUT5, DOUT4, DOUT3, DOUT2, DOUT1, DOUT0, POWER_EN, PWDN
SPI: NSS, SCK, CIPO, COPI
BLE CTRL: HOST WAKE, DEVICE WAKE, ON
WiFi CTRL: HOST WAKE, ON
QSPI: SCK, ~{CS}, IO0, IO1, IO2, IO3
JTAG: ~{RESET}, TCK/SCK, TDI, TDO/SWO, TMS/SWD, TRST

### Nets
+3V3: C1.2 C5.2 C6.2 C7.2 C8.2 C9.2 C10.2 C11.2 C12.2 C13.2 C14.2 C15.2 C16.2 C17.2 C18.2 C19.2 C21.2 C22.2 C23.2 C24.2 C25.2 C26.2 C27.2 C28.2 C29.2 C30.2 C31.2 C57.2 C73.2 C74.2 C75.2 C76.2 C77.2 C78.2 C79.2 C80.2 C81.2 C82.2 C83.2 L4.1 R3.1 R5.1 R19.2 R20.2 R21.1 R26.2 R27.2 R28.2 R29.2 U1.A6(VDDLDO) U1.C17(VDDLDO) U1.E6(VDD) U1.E9(VDD) U1.E11(VDD) U1.F5(VDD) U1.F17(VDD33USB) U1.G5(VDD) U1.G13(VDD) U1.H5(VDD) U1.H13(VDD) U1.J13(VDD) U1.K5(VDD) U1.K13(VDD) U1.L5(VDD) U1.L13(VDD) U1.M5(VDD) U1.M13(VDD) U1.N7(VDD) U1.N8(VDD) U1.N10(VDD) U1.N11(VDD) U1.N12(VDD) U1.P17(VDDDSI) U1.U12(VDDLDO) U3.A7(VDDQ) U3.A9(VDD) U3.B3(VDDQ) U3.C7(VDDQ) U3.D3(VDDQ) U3.E7(VDD) U3.J9(VDD) U8.8(VCC) Y1.3(VDD)
GND: C1.1 C5.1 C6.1 C7.1 C8.1 C9.1 C10.1 C11.1 C12.1 C13.1 C14.1 C15.1 C16.1 C17.1 C18.1 C19.1 C21.1 C22.1 C23.1 C24.1 C25.1 C26.1 C27.1 C28.1 C29.1 C30.1 C31.1 C32.1 C33.1 C34.1 C35.1 C36.1 C51.2 C52.2 C53.2 C54.2 C57.1 C72.2 C73.1 C74.1 C75.1 C76.1 C77.1 C78.1 C79.1 C80.1 C81.1 C82.1 C83.1 R4.2 U1.A1(VSS) U1.A17(VSS) U1.B2(VSS) U1.B6(VSS) U1.C10(VSS) U1.C13(VSS) U1.C16(VSS) U1.F1(VDDSMPS) U1.F2(VSSSMPS) U1.G2(VFBSMPS) U1.G7(VSS) U1.G8(VSS) U1.G9(VSS) U1.G10(VSS) U1.G11(VSS) U1.G16(VSS) U1.H7(VSS) U1.H8(VSS) U1.H9(VSS) U1.H10(VSS) U1.H11(VSS) U1.J3(VSS) U1.J7(VSS) U1.J8(VSS) U1.J9(VSS) U1.J10(VSS) U1.J11(VSS) U1.J16(VSS) U1.J17(VSS) U1.K7(VSS) U1.K8(VSS) U1.K9(VSS) U1.K10(VSS) U1.K11(VSS) U1.K15(VSSDSI) U1.L7(VSS) U1.L8(VSS) U1.L9(VSS) U1.L10(VSS) U1.L11(VSS) U1.L15(VSSDSI) U1.M15(VSSDSI) U1.N1(VREF-) U1.N16(VSS) U1.P1(VSSA) U1.R4(VSS) U1.R8(VSS) U1.T12(VSS) U1.U1(VSS) U1.U17(VSS) U3.A1(VSS) U3.A3(VSSQ) U3.B7(VSSQ) U3.C3(VSSQ) U3.D7(VSSQ) U3.E3(VSS) U3.J1(VSS) U8.4(GND) U8.9(PAD) Y1.1(GND) Y1.4(GND)
DSI_CK_N: U1.L17(DSI_CKN) ; port DSI.CLK_N
DSI_CK_P: U1.L16(DSI_CKP) ; port DSI.CLK_P
DSI_D0_N: U1.M17(DSI_D0N) ; port DSI.D0_N
DSI_D0_P: U1.M16(DSI_D0P) ; port DSI.D0_P
DSI_D1_N: U1.K17(DSI_D1N) ; port DSI.D1_N
DSI_D1_P: U1.K16(DSI_D1P) ; port DSI.D1_P
MEMS_32.768kHz: C72.1 R6.2 Y1.2(CLK) ; port MEMS_32.768kHz
~{NRST}: R21.2 U1.K1(NRST) ; port JTAG.~{RESET}  [project net JTAG.~{RESET}]
PA0: U1.N5(PA0) ; port ANALOG.A7  [project net MIC]
PA0_C: U1.T1(PA0_C) ; port ANALOG.A11
PA1: U1.N4(PA1) ; port CAMERA.POWER_EN
PA1_C: U1.T2(PA1_C) ; port ANALOG.A10
PA2: U1.N3(PA2) ; port PA2
PA3: U1.U2(PA3) ; port PA3
PA4: U1.U3(PA4) ; port ANALOG.DAC0
PA5: U1.T3(PA5) ; port ANALOG.DAC1  [project net LEFT]
PA6: U1.R3(PA6) ; port CAMERA.PCLK
PA7: U1.R5(PA7) ; port PA7
PA8: U1.E15(PA8) ; port UART7.RX
PA9: U1.D15(PA9) ; port USART1.TX
PA10: U1.D14(PA10) ; port BLE_CTRL.ON
PA13: U1.C15(PA13(JTMS/SWDIO)) ; port JTAG.TMS/SWD  [project net JTAG.TMS/SWD]
PA14: U1.B14(PA14(JTCK/SWCLK)) ; port JTAG.TCK/SCK  [project net JTAG.TCK/SCK]
PA15: U1.A14(PA15(JTDI)) ; port PA15
PB0: U1.U5(PB0) ; port ANALOG.A2
PB1: U1.T5(PB1) ; port ANALOG.A3
PB2: U1.R6(PB2) ; port SAI1.SD_A
PB3: U1.C6(PB3(JTDO/TRACESWO)) ; port SPI1.SCK
PB4: U1.B7(PB4(NJTRST)) ; port PB4
PB5: U1.A5(PB5) ; port FDCAN2.RX
PB6: R26.1 U1.B5(PB6) ; port I2C4.SCL, port CAMERA.SCL  [project net I2C4.SCL]
PB7: U1.C5(PB7) ; port USART1.RX
PB8: R29.1 U1.D5(PB8) ; port I2C1.SCL
PB9: R28.1 U1.D4(PB9) ; port I2C1.SDA
PB10: U1.P11(PB10) ; port WIFI_CTRL.ON
PB11: R19.1 U1.P12(PB11) ; port I2C2.SDA
PB12: U1.T14(PB12) ; port PB12
PB13: U1.U14(PB13) ; port FDCAN2.TX
PC0: U1.L2(PC0) ; port ANALOG.A6
PC1: U1.M2(PC1) ; port DFSDM1.DATIN0
PC2: U1.M3(PC2) ; port ANALOG.A5
PC2_C: U1.R1(PC2_C) ; port ANALOG.A8
PC3: U1.M4(PC3) ; port ANALOG.A4
PC3_C: U1.R2(PC3_C) ; port ANALOG.A9
PC4: U1.T4(PC4) ; port ANALOG.A0
PC5: U1.U4(PC5) ; port ANALOG.A1
PC6: U1.F14(PC6) ; port I2S2.MCK
PC7: U1.F13(PC7) ; port USART6.RX
PC8: U1.E13(PC8) ; port SDIO.D0
PC9: U1.E14(PC9) ; port SDIO.D1
PC10: U1.A13(PC10) ; port SDIO.D2
PC11: U1.B13(PC11) ; port SDIO.D3
PC12: U1.C12(PC12) ; port SDIO.CLK
PC13: R4.1 U1.E3(PC13) U1.E8(BOOT0) ; port BOOT, port PC13
PD0: U1.D13(PD0) U3.C9(DQ3)  [project net PD0_5]
PD1: U1.E12(PD1) U3.B8(DQ2)  [project net PD1_5]
PD2: U1.D12(PD2) ; port SDIO.CMD
PD3: U1.B12(PD3) ; port DFSDM1.CKOUT
PD4: U1.A12(PD4) ; port CAMERA.PWDN
PD5: U1.A11(PD5) ; port USART2.TX
PD6: U1.B11(PD6) ; port USART2.RX
PD7: U1.C11(PD7) ; port SPI1.COPI
PD8: U1.U16(PD8) U3.B2(DQ13)  [project net PD8_5]
PD9: U1.T17(PD9) U3.B1(DQ14)  [project net PD9_5]
PD10: U1.T16(PD10) U3.A2(DQ15)  [project net PD10_5]
PD11: U1.R15(PD11) U8.5(IO0(SI)) ; harness QSPI.IO0
PD12: U1.R16(PD12) U8.2(IO1(SO)) ; harness QSPI.IO1
PD13: U1.R17(PD13) ; port PD13
PD14: U1.P16(PD14) U3.A8(DQ0)  [project net PD14_5]
PD15: U1.P15(PD15) U3.B9(DQ1)  [project net PD15_5]
PE0: U1.C4(PE0) U3.E8(DQML)  [project net PE0_5]
PE1: U1.B4(PE1) U3.F1(DQMH)  [project net PE1_5]
PE2: U1.C3(PE2) U8.3(IO2~{(WP})) ; harness QSPI.IO2
PE3: U1.D3(PE3) ; port PE3
PE4: U1.D2(PE4) ; port SAI1.FS_A
PE5: U1.D1(PE5) ; port SAI1.SCK_A
PE6: U1.E5(PE6) ; port LTDC.G1
PE7: U1.U9(PE7) U3.C8(DQ4)  [project net PE7_5]
PE8: U1.T9(PE8) U3.D9(DQ5)  [project net PE8_5]
PE9: U1.P9(PE9) U3.D8(DQ6)  [project net PE9_5]
PE10: U1.N9(PE10) U3.E9(DQ7)  [project net PE10_5]
PE11: U1.P10(PE11) U3.E1(DQ8)  [project net PE11_5]
PE12: U1.R10(PE12) U3.D2(DQ9)  [project net PE12_5]
PE13: U1.T10(PE13) U3.D1(DQ10)  [project net PE13_5]
PE14: U1.U10(PE14) U3.C2(DQ11)  [project net PE14_5]
PE15: U1.R11(PE15) U3.C1(DQ12)  [project net PE15_5]
PF0: U1.G4(PF0) U3.H7(A0)  [project net PF0_5]
PF1: U1.G3(PF1) U3.H8(A1)  [project net PF1_5]
PF2: U1.G1(PF2) U3.J8(A2)  [project net PF2_5]
PF3: U1.H4(PF3) U3.J7(A3)  [project net PF3_5]
PF4: U1.J5(PF4) U3.J3(A4)  [project net PF4_5]
PF5: U1.J4(PF5) U3.J2(A5)  [project net PF5_5]
PF6: U1.K2(PF6) U8.7(IO3~{(HOLD})) ; harness QSPI.IO3
PF7: U1.K3(PF7) ; port UART7.TX
PF8: U1.K4(PF8) ; port UART7.RTS
PF9: U1.L4(PF9) ; port UART7.CTS
PF10: U1.L3(PF10) U8.6(SCK) ; harness QSPI.SCK
PF11: U1.T7(PF11) U3.F8(RAS#)  [project net PF11_5]
PF12: U1.R7(PF12) U3.H3(A6)  [project net PF12_5]
PF13: U1.P7(PF13) U3.H2(A7)  [project net PF13_5]
PF14: U1.P8(PF14) U3.H1(A8)  [project net PF14_5]
PF15: U1.R9(PF15) U3.G3(A9)  [project net PF15_5]
PG0: U1.T8(PG0) U3.H9(A10)  [project net PG0_5]
PG1: U1.U8(PG1) U3.G2(A11)  [project net PG1_5]
PG2: U1.H16(PG2) U3.G1(NC/A12)  [project net PG2_5]
PG3: U1.H15(PG3) ; port BLE_CTRL.HOST WAKE
PG4: U1.H14(PG4) U3.G7(BA0)  [project net PG4_5]
PG5: U1.G14(PG5) U3.G8(BA1)  [project net PG5_5]
PG6: U1.G15(PG6) U8.1(~{CS}) ; harness QSPI.~{CS}
PG7: U1.F16(PG7) ; port SAI1.MCLK_A
PG8: U1.F15(PG8) U3.F2(CLK)  [project net PG8_5]
PG9: U1.A10(PG9) ; port SPI1.CIPO
PG10: U1.A9(PG10) ; port LTDC.G3
PG11: U1.B9(PG11) ; port CAMERA.DOUT3
PG12: U1.C9(PG12) ; port LTDC.B1
PG13: U1.D9(PG13) ; port LTDC.R0
PG14: U1.D8(PG14) ; port USART6.TX
PG15: U1.D6(PG15) U3.F7(CAS#)  [project net PG15_5]
PH2: U1.N2(PH2) U3.F3(CKE)  [project net PH2_5]
PH3: U1.P2(PH3) U3.G9(CS#)  [project net PH3_5]
PH4: R20.1 U1.P3(PH4) ; port I2C2.SCL
PH5: U1.P4(PH5) U3.F9(WE#)  [project net PH5_5]
PH6: U1.T11(PH6) ; port SPI5.SCK
PH7: U1.U13(PH7) ; port BLE_CTRL.DEVICE WAKE
PH8: U1.T13(PH8) ; port CAMERA.HREF
PH9: U1.R13(PH9) ; port CAMERA.DOUT0
PH10: U1.P13(PH10) ; port CAMERA.DOUT1
PH11: U1.P14(PH11) ; port CAMERA.DOUT2
PH12: R27.1 U1.R14(PH12) ; port I2C4.SDA, port CAMERA.SDATA  [project net I2C4.SDA]
PH13: U1.D16(PH13) ; port USART4.TX
PH14: U1.B17(PH14) ; port CAMERA.DOUT4
PH15: U1.B16(PH15) ; port LTDC.G4
PI0: U1.A16(PI0) ; port I2S2.WS
PI1: U1.A15(PI1) ; port I2S2.CK
PI2: U1.B15(PI2) ; port I2S2.SDI
PI3: U1.C14(PI3) ; port I2S2.SDO
PI4: U1.A4(PI4) ; port CAMERA.DOUT5
PI5: U1.A3(PI5) ; port CAMERA.VSYNC
PI6: U1.A2(PI6) ; port CAMERA.DOUT6
PI7: U1.B3(PI7) ; port CAMERA.DOUT7
PI8: U1.E4(PI8) ; port WIFI_CTRL.HOST WAKE
PI9: U1.E2(PI9) ; port USART4.RX
PI10: U1.F3(PI10) ; port LTDC.HSYNC
PI11: U1.F4(PI11) ; port LTDC.G6
PI12: U1.H1(PI12) ; port PI12
PI13: U1.H2(PI13) ; port LTDC.VSYNC
PI14: U1.H3(PI14) ; port LTDC.CLK
PI15: U1.P5(PI15) ; port LTDC.G2
PJ0: U1.N6(PJ0) ; port LTDC.R1
PJ1: U1.P6(PJ1) ; port LTDC.R2
PJ2: U1.T6(PJ2) ; port LTDC.R3
PJ3: U1.U6(PJ3) ; port LTDC.R4
PJ4: U1.U7(PJ4) ; port LTDC.R5
PJ5: U1.R12(PJ5) ; port LTDC.R6
PJ6: U1.N15(PJ6) ; port LTDC.R7
PJ7: U1.N14(PJ7) ; port LTDC.G0
PJ8: U1.N13(PJ8) ; port PJ8
PJ9: U1.M14(PJ9) ; port CAMERA.XCLK
PJ10: U1.L14(PJ10) ; port SPI5.COPI
PJ11: U1.K14(PJ11) ; port SPI5.CIPO
PJ12: U1.D11(PJ12) ; port LTDC.B0
PJ13: U1.E10(PJ13) ; port PJ13
PJ14: U1.D10(PJ14) ; port LTDC.B2
PJ15: U1.B10(PJ15) ; port LTDC.B3
PK0: U1.J14(PK0) ; port LTDC.G5
PK1: U1.J15(PK1) ; port SPI5.NSS
PK2: U1.H17(PK2) ; port LTDC.G7
PK3: U1.C8(PK3) ; port LTDC.B4
PK4: U1.B8(PK4) ; port LTDC.B5
PK5: U1.A8(PK5) ; port LTDC.B6
PK6: U1.C7(PK6) ; port LTDC.B7
PK7: U1.D7(PK7) ; port LTDC.DE
USBFS_D_N: U1.E17(PA11) ; port USB_FS.D_N  [project net USB0_D_N]
USBFS_D_P: U1.E16(PA12) ; port USB_FS.D_P  [project net USB0_D_P]
USBHS_D_N: U1.U15(PB14) ; port USB_HS.D_N  [project net USB1_D_N]
USBHS_D_P: U1.T15(PB15) ; port USB_HS.D_P  [project net USB1_D_P]
VCAP_A7: C34.2 U1.A7(VCAP)  [project net VCAP_A7_5]
VCAP_D17: C33.2 U1.D17(VCAP)  [project net VCAP_D17_5]
VCAP_U11: C32.2 U1.U11(VCAP)  [project net VCAP_U11_5]
NetC35_2: C35.2 U1.N17(VCAPDSI)
NetC36_2: C36.2 L4.2 R7.2 U1.L1(VDDA)
NetC51_1: C51.1 R8.1 Y2.2
NetC52_1: C52.1 U1.J2(PH0-OSCIN) Y3.3
NetC53_1: C53.1 U1.C1(PC15-OSC32_OUT) Y2.1
NetC54_1: C54.1 U1.J1(PH1-OSCOUT) Y3.1
NetJ1_3: U1.B1(VBAT) ; port VBAT
NetJDIGITAL_3: R7.1 U1.M1(VREF+) ; port VREF_P
NetR3_2: R3.2 U1.E7(PDR_ON)
NetR5_2: R5.2 U1.G17(VDD50USB)
NetR6_1: R6.1 R8.2 U1.C2(PC14-OSC32_IN)

Not connected (* = marked no-connect by the designer): U1 E1(VLXSMPS)*; U3 E2(NC)*; Y3 2(NC)* 4(NC)*

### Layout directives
differential pair; differential pair class USB: USB0_D_N, USB0_D_P, USB1_D_N, USB1_D_P
differential pair; differential pair class DSI: DSI_CK_N, DSI_CK_P, DSI_D0_N, DSI_D0_P, DSI_D1_N, DSI_D1_P
net class RAM: PD0, PD1, PD8, PD9, PD10, PD14, PD15, PE0, PE1, PE7, PE8, PE9, PE10, PE11, PE12, PE13, PE14, PE15, PF0, PF1, PF2, PF3, PF4, PF5, PF11, PF12, PF13, PF14, PF15, PG0, PG1, PG2, PG4, PG5, PG8, PG15, PH2, PH3, PH5
net class ANALOG: PA0, PA0_C, PA1_C, PA4, PA5, PB0, PB1, PC0, PC2, PC2_C, PC3, PC3_C, PC4, PC5
net class FLASH: PD11, PD12, PE2, PF6, PF10, PG6

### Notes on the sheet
- Flash 128Mb
- (near U3) SDRAM 64Mb
- MEMS 32.768kHz
- Alternative to 32.768kHz crystal, normally DNP
- BOOT0
- RGB RED
- RGB BLUE
- RGB GREEN
- PA12
- PA11
- PB15
- PB14
- ALSO LPUART1
- COMP1_INM
- OPAMP1_VOUT
- OPAMP1_VINM
- ADC12_INP4
- ADC12_INP4, INP8
- AS PER STANDARD MOUNTING OPTION:
  VDDA CONNECTED THROUGH A FERRITE TO VDD
  VREFp CONNECTED TO VDDA
  VREFn CONNECTED TO GND
- COMP1_INP
- OPAMP1_VINP
- ADC12_INN5, INP9
- ADC12_INP5
- ADC12_INN12, INP13
- ADC123_INN11, INP12
- ADC123_INP10
- ADC3_INN1, INP0
- ADC3_INP1
- ADC12_INP1
- ADC12_INN1, INP0
- ADC1_INP16
- DAC1_OUT2
- DAC1_OUT1
- ADC12_INN18, INP19

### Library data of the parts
C1 C5-C11 C16-C19 C21-C31 C57 C77-C79 C83 = C0015-A.14: as C20 on sheet POWER
C12 C36 C73-C76 C80-C82 = C0091-A.13: CAP CHIP 0402 10uF 20% X5R 6.3V; Manufacturer: Murata; Code Arduino: C0091
C13-C15 C32-C35 = C0031-A.14: as C50 on sheet POWER
C51 C53 = C0026-A.14: CAP CHIP 0402 18pF 5% C0G 50V; Manufacturer: KEMET; Code Arduino: 2320
C52 C54 = C0006-A.14: CAP CHIP 0402 10pF 5% 50V C0G; Manufacturer: KEMET; Code Arduino: 3382
C72 = UT0021-A.3: DNP CAP 0402
L4 = I0063-A.3: IND 47uH 20% Isat 20mA f 10MHz 0603; Manufacturer: Murata; Series Resistance: 2.55; Max DC Current: 180mA; Code Arduino: I0063
R3 R4 R21 = R0001-A.23: as R30 on sheet POWER
R5 = R0000-A.23: RES CHIP 0402 0R 1/16W; Manufacturer: Vishay; Code Arduino: 0039; Tolerance: 0%; Power: 62.5mW; Temperature coefficient: 0ppm
R6 R8 = R0000-A.23: as R22 on sheet AUDIO
R7 = R0017-A.23: RES CHIP 0402 330R 5% 1/16W; Manufacturer: Vishay; Code Arduino: 2229; Power: 62.5mW; Temperature coefficient: 200ppm
R19 R20 R26-R29 = R0210-A.18: as R36 on sheet POWER
U1 = U0020-A.8: IC MCU Cortex M7 + Cortex M4; Manufacturer: ST Microelectronics; Code Arduino: A5524
U3 = U0122-A.4: IC SDRAM 64 Mb PC133 SDR; Manufacturer: Alliance Memory; Code Arduino: U0122
U8 = U0197-A.9: IC FLASH 128MB 6DFN 3V; Manufacturer: Adesto Technologies; Code Arduino: U0197
Y1 = X0002-A.6: MEMS OSC XO 32.7680KHZ LVCMOS; Manufacturer: SiTIME; Frequency: 32.768kHz; Min Supply Voltage: 1.5V; Current Rating: 1.35uA; Load Capacitance: 10pF; Max Supply Current: 1.4uA; Code Arduino: X0002; Frequency Stability: 100ppm; Max Duty Cycle: 52%; Max Supply Voltage: 3.63V
Y2 = X0003-A.5: CRYSTAL 32.768kHz 20ppm 12.5pF SMD 1.6x0.9mm; Manufacturer: Citizen FineDevice; Series Resistance: 70kR; Code Arduino: 0213; Frequency Stability: 0.12%
Y3 = X0019-A.12: CRYSTAL 16.0000MHz 12pF SMD; Manufacturer: Fronter Electronics; Frequency: 16MHz; Code Arduino: 0395

## Sheet HEADERS.SchDoc: HEADERS
size A3; Author: Silvio Navaretti; CompanyName: Arduino srl; DocumentNumber: ABX00063; Revision: V1.2; SheetNumber: 2; SheetTotal: 8; RevAuthor: Silvio Navaretti
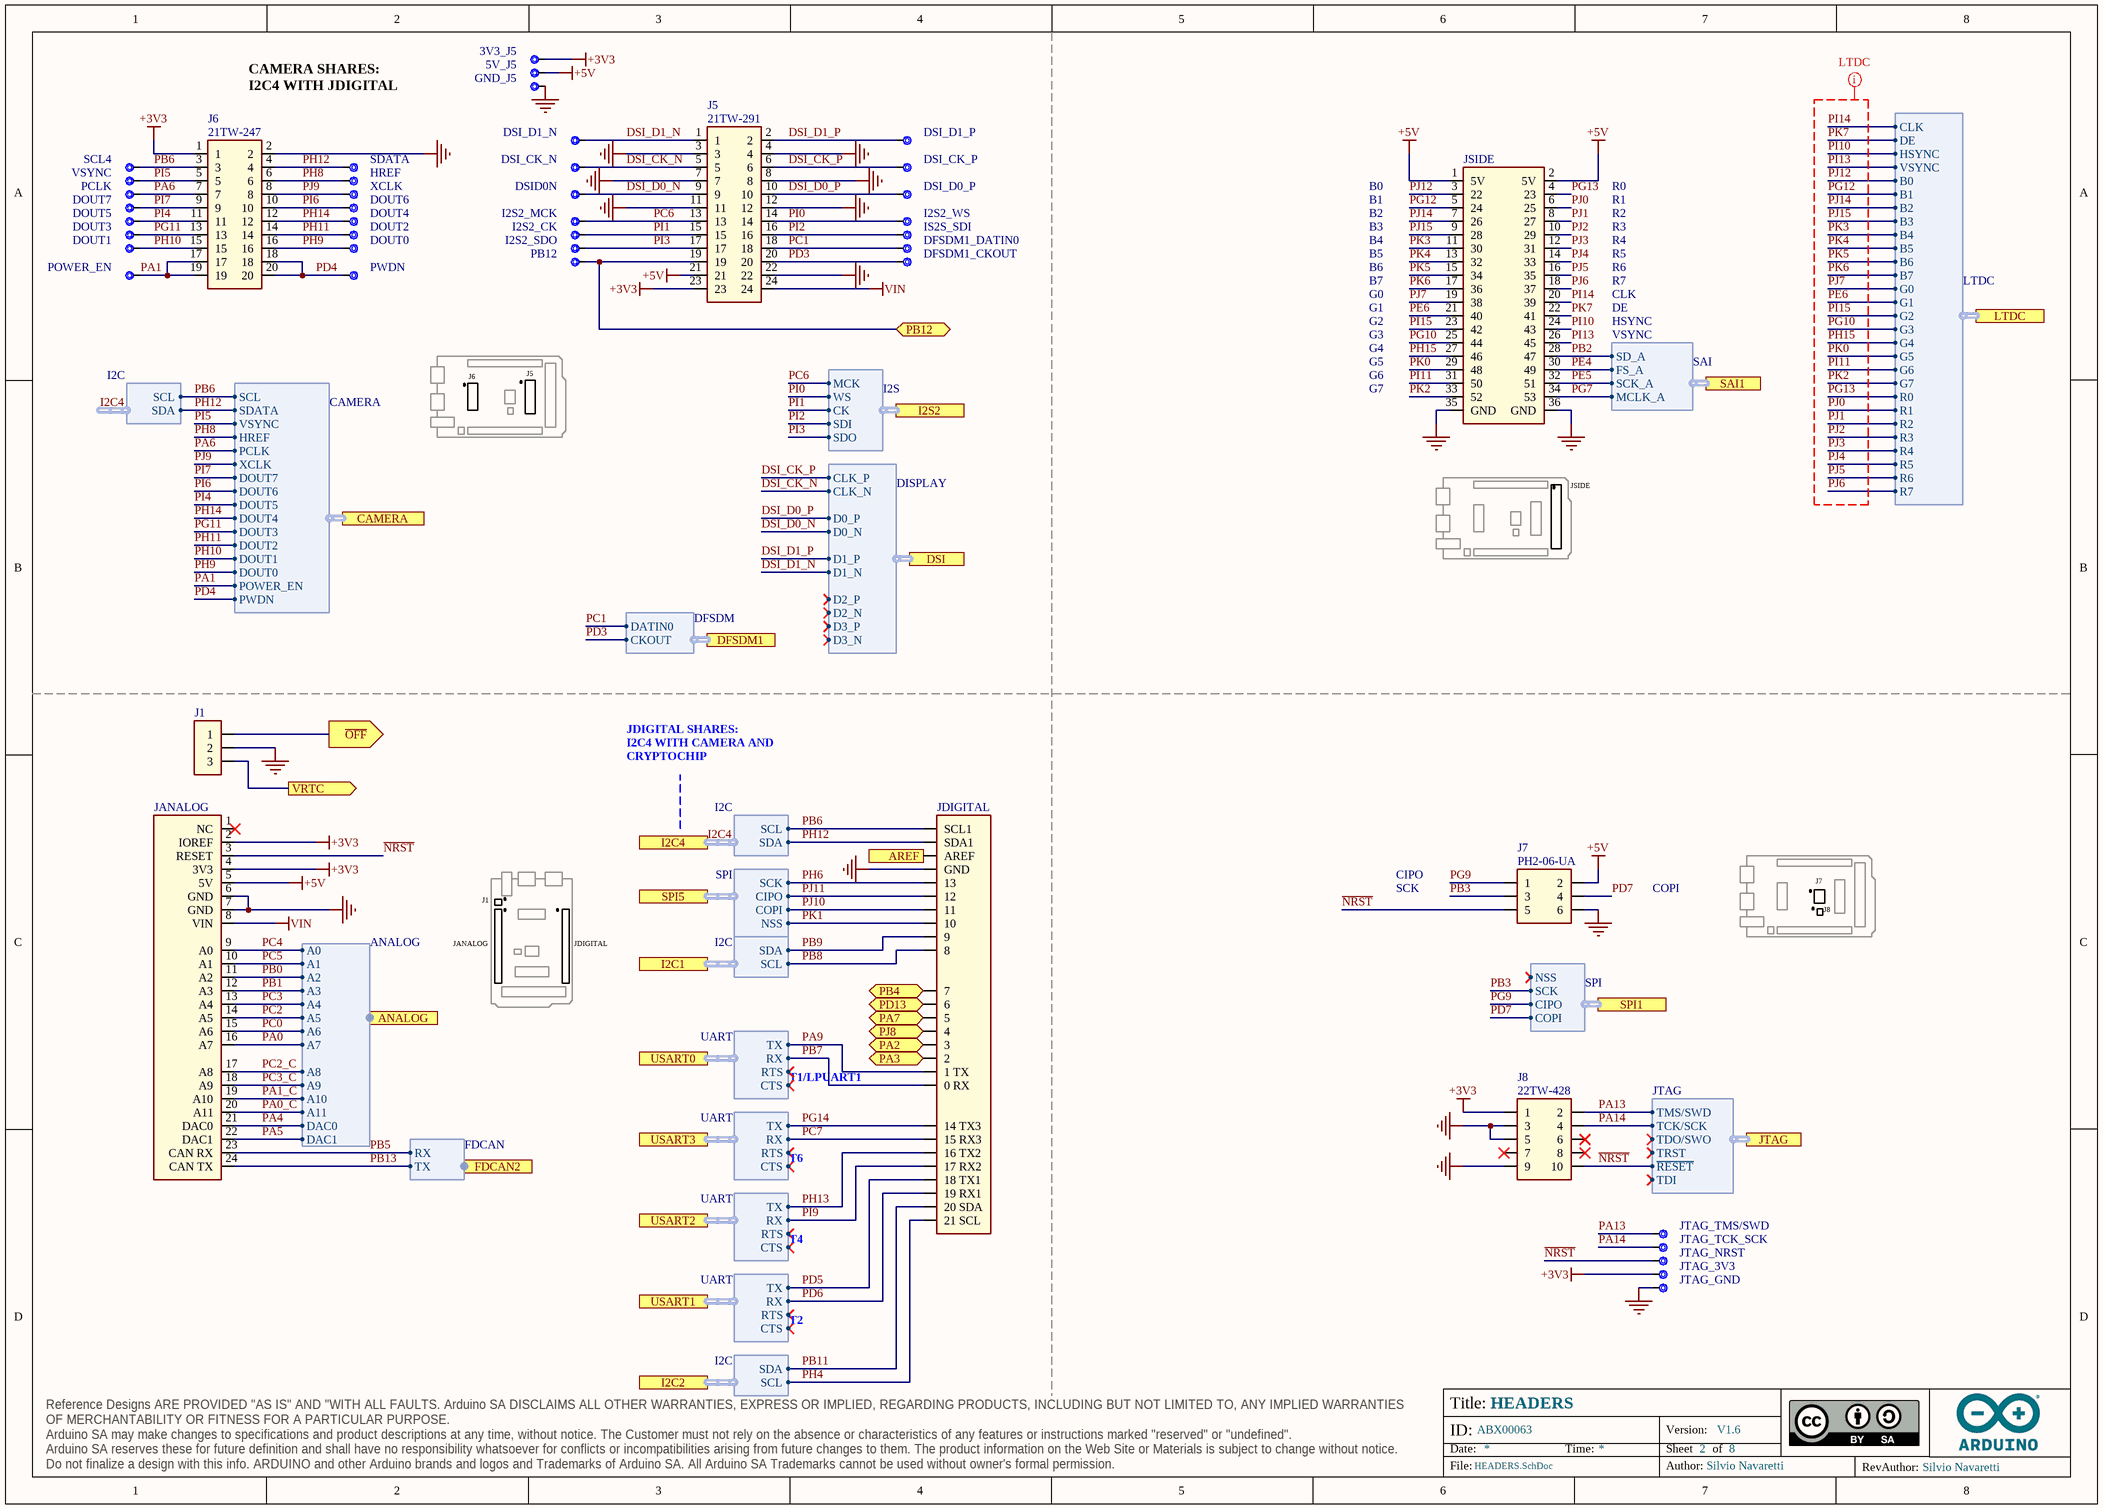
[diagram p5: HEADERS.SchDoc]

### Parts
3V3_J5  CMP-018-0005-A.3  [TP-1.00MM]  (value not drawn)  (no BOM)
5V_J5  CMP-018-0005-A.3  [TP-1.00MM]  (value not drawn)  (no BOM)
DFSDM1_CKOUT  CMP-018-0005-A.3  [TP-1.00MM]  (value not drawn)  (no BOM)
DFSDM1_DATIN0  CMP-018-0005-A.3  [TP-1.00MM]  (value not drawn)  (no BOM)
DOUT0  CMP-018-0005-A.3  [TP-1.00MM]  (value not drawn)  (no BOM)
DOUT1  CMP-018-0005-A.3  [TP-1.00MM]  (value not drawn)  (no BOM)
DOUT2  CMP-018-0005-A.3  [TP-1.00MM]  (value not drawn)  (no BOM)
DOUT3  CMP-018-0005-A.3  [TP-1.00MM]  (value not drawn)  (no BOM)
DOUT4  CMP-018-0005-A.3  [TP-1.00MM]  (value not drawn)  (no BOM)
DOUT5  CMP-018-0005-A.3  [TP-1.00MM]  (value not drawn)  (no BOM)
DOUT6  CMP-018-0005-A.3  [TP-1.00MM]  (value not drawn)  (no BOM)
DOUT7  CMP-018-0005-A.3  [TP-1.00MM]  (value not drawn)  (no BOM)
DSI_CK_N  CMP-018-0005-A.3  [TP-1.00MM]  (value not drawn)  (no BOM)
DSI_CK_P  CMP-018-0005-A.3  [TP-1.00MM]  (value not drawn)  (no BOM)
DSI_D0_P  CMP-018-0005-A.3  [TP-1.00MM]  (value not drawn)  (no BOM)
DSI_D1_N  CMP-018-0005-A.3  [TP-1.00MM]  (value not drawn)  (no BOM)
DSI_D1_P  CMP-018-0005-A.3  [TP-1.00MM]  (value not drawn)  (no BOM)
DSID0N  CMP-018-0005-A.3  [TP-1.00MM]  (value not drawn)  (no BOM)
GND_J5  CMP-018-0005-A.3  [TP-1.00MM]  (value not drawn)  (no BOM)
HREF  CMP-018-0005-A.3  [TP-1.00MM]  (value not drawn)  (no BOM)
I2S2_CK  CMP-018-0005-A.3  [TP-1.00MM]  (value not drawn)  (no BOM)
I2S2_MCK  CMP-018-0005-A.3  [TP-1.00MM]  (value not drawn)  (no BOM)
I2S2_SDO  CMP-018-0005-A.3  [TP-1.00MM]  (value not drawn)  (no BOM)
I2S2_WS  CMP-018-0005-A.3  [TP-1.00MM]  (value not drawn)  (no BOM)
IS2S_SDI  CMP-018-0005-A.3  [TP-1.00MM]  (value not drawn)  (no BOM)
J1  HEADER TH 2.54mm VERT. 1x003POS  [PIN HEADER 2.54mm VERT. 1x3POS]  (value not drawn)  (no BOM)
J5  21TW-291  [21TW-291]
J6  21TW-247  [21TW-247]
J7  PH2-06-UA  [2X03]
J8  22TW-428  [FTSH-105-01-F-DV-Footprint-1]
JANALOG  20TW-887  [GIGA header custom analog]  (value not drawn)
JDIGITAL  20TW-890  [GIGA Header custom digital]  (value not drawn)
JSIDE  20TW-891  [GIGA custom header side-Footprint-1]  (value not drawn)
JTAG_3V3  CMP-018-0005-A.3  [TP-1.00MM]  (value not drawn)  (no BOM)
JTAG_GND  CMP-018-0005-A.3  [TP-1.00MM]  (value not drawn)  (no BOM)
JTAG_NRST  CMP-018-0005-A.3  [TP-1.00MM]  (value not drawn)  (no BOM)
JTAG_TCK_SCK  CMP-018-0005-A.3  [TP-1.00MM]  (value not drawn)  (no BOM)
JTAG_TMS/SWD  CMP-018-0005-A.3  [TP-1.00MM]  (value not drawn)  (no BOM)
PB12  CMP-018-0005-A.3  [TP-1.00MM]  (value not drawn)  (no BOM)
PCLK  CMP-018-0005-A.3  [TP-1.00MM]  (value not drawn)  (no BOM)
POWER_EN  CMP-018-0005-A.3  [TP-1.00MM]  (value not drawn)  (no BOM)
PWDN  CMP-018-0005-A.3  [TP-1.00MM]  (value not drawn)  (no BOM)
SCL4  CMP-018-0005-A.3  [TP-1.00MM]  (value not drawn)  (no BOM)
SDATA  CMP-018-0005-A.3  [TP-1.00MM]  (value not drawn)  (no BOM)
VSYNC  CMP-018-0005-A.3  [TP-1.00MM]  (value not drawn)  (no BOM)
XCLK  CMP-018-0005-A.3  [TP-1.00MM]  (value not drawn)  (no BOM)

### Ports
ANALOG (harness ANALOG), AREF (out), CAMERA (harness CAMERA), DFSDM1 (harness DFSDM), DSI (harness DISPLAY), FDCAN2 (harness FDCAN), I2C1 (harness I2C), I2C2 (harness I2C), I2C4 (harness I2C), I2S2 (harness I2S), JTAG (harness JTAG), LTDC (harness LTDC), PA2 (bidir), PA3 (bidir), PA7 (bidir), PB4 (bidir), PB12 (bidir), PD13 (bidir), PJ8 (bidir), SAI1 (harness SAI), SPI1 (harness SPI), SPI5 (harness SPI), USART0 (harness UART), USART1 (harness UART), USART2 (harness UART), USART3 (harness UART), VRTC (out), ~{OFF} (out)

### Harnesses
SPI: NSS, SCK, CIPO, COPI
I2C: SDA, SCL
LTDC: B0, B1, B2, B3, B4, B5, B6, B7, CLK, DE, G0, G1, G2, G3, G4, G5, G6, G7, HSYNC, R0, R1, R2, R3, R4, R5, R6, R7, VSYNC
SAI: SD_A, FS_A, SCK_A, MCLK_A
ANALOG: A0, A1, A2, A3, A7, A6, A5, A4, A8, A9, A10, A11, DAC0, DAC1
I2S: CK, SDI, SDO, WS, MCK
DISPLAY: CLK_N, CLK_P, D0_N, D0_P, D1_N, D1_P, D2_N, D2_P, D3_N, D3_P
DFSDM: DATIN0, CKOUT
CAMERA: SCL, SDATA, VSYNC, HREF, PCLK, XCLK, DOUT7, DOUT6, DOUT5, DOUT4, DOUT3, DOUT2, DOUT1, DOUT0, POWER_EN, PWDN
JTAG: ~{RESET}, TCK/SCK, TDI, TDO/SWO, TMS/SWD, TRST
UART: RX, TX, RTS, CTS
FDCAN: RX, TX

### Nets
+3V3: 3V3_J5.X J5.23 J6.1 J8.1 JANALOG.2(IOREF) JANALOG.4(3V3) JTAG_3V3.X
+5V: 5V_J5.X J5.21 J7.2 JANALOG.5(5V) JSIDE.1(5V) JSIDE.2(5V)
GND: GND_J5.X J1.2 J5.3 J5.4 J5.7 J5.8 J5.11 J5.12 J5.22 J6.2 J7.6 J8.3 J8.5 J8.9 JANALOG.6(GND) JANALOG.7(GND) JDIGITAL.4(GND) JSIDE.35(GND) JSIDE.36(GND) JTAG_GND.X
VIN: J5.24 JANALOG.8(VIN)
DSI_CK_N: DSI_CK_N.X J5.5 ; port DSI.CLK_N
DSI_CK_P: DSI_CK_P.X J5.6 ; port DSI.CLK_P
DSI_D0_N: DSID0N.X J5.9 ; port DSI.D0_N
DSI_D0_P: DSI_D0_P.X J5.10 ; port DSI.D0_P
DSI_D1_N: DSI_D1_N.X J5.1 ; port DSI.D1_N
DSI_D1_P: DSI_D1_P.X J5.2 ; port DSI.D1_P
~{NRST}: J7.5 J8.10 JANALOG.3(RESET) JTAG_NRST.X ; port JTAG.~{RESET}  [project net JTAG.~{RESET}]
PA0: JANALOG.16(A7) ; port ANALOG.A7  [project net MIC]
PA0_C: JANALOG.20(A11) ; port ANALOG.A11
PA1: J6.17 J6.19 POWER_EN.X ; port CAMERA.POWER_EN
PA1_C: JANALOG.19(A10) ; port ANALOG.A10
PA2: JDIGITAL.15(3) ; port PA2
PA3: JDIGITAL.16(2) ; port PA3
PA4: JANALOG.21(DAC0) ; port ANALOG.DAC0
PA5: JANALOG.22(DAC1) ; port ANALOG.DAC1  [project net LEFT]
PA6: J6.7 PCLK.X ; port CAMERA.PCLK
PA7: JDIGITAL.13(5) ; port PA7
PA9: JDIGITAL.17(1_TX) ; port USART0.TX
PA13: J8.2 JTAG_TMS/SWD.X ; port JTAG.TMS/SWD  [project net JTAG.TMS/SWD]
PA14: J8.4 JTAG_TCK_SCK.X ; port JTAG.TCK/SCK  [project net JTAG.TCK/SCK]
PB0: JANALOG.11(A2) ; port ANALOG.A2
PB1: JANALOG.12(A3) ; port ANALOG.A3
PB2: JSIDE.28(47) ; port SAI1.SD_A
PB3: J7.3 ; port SPI1.SCK
PB4: JDIGITAL.11(7) ; port PB4
PB5: JANALOG.23(CAN_RX) ; port FDCAN2.RX
PB6: J6.3 JDIGITAL.1(SCL1) SCL4.X ; port CAMERA.SCL, port I2C4.SCL  [project net I2C4.SCL]
PB7: JDIGITAL.18(0_RX) ; port USART0.RX
PB8: JDIGITAL.10(8) ; port I2C1.SCL
PB9: JDIGITAL.9 ; port I2C1.SDA
PB11: JDIGITAL.25(20_SDA) ; port I2C2.SDA
PB12: J5.19 PB12.X ; port PB12
PB13: JANALOG.24(CAN_TX) ; port FDCAN2.TX
PC0: JANALOG.15(A6) ; port ANALOG.A6
PC1: DFSDM1_DATIN0.X J5.18 ; port DFSDM1.DATIN0
PC2: JANALOG.14(A5) ; port ANALOG.A5
PC2_C: JANALOG.17(A8) ; port ANALOG.A8
PC3: JANALOG.13(A4) ; port ANALOG.A4
PC3_C: JANALOG.18(A9) ; port ANALOG.A9
PC4: JANALOG.9(A0) ; port ANALOG.A0
PC5: JANALOG.10(A1) ; port ANALOG.A1
PC6: I2S2_MCK.X J5.13 ; port I2S2.MCK
PC7: JDIGITAL.20(15_RX3) ; port USART3.RX
PD3: DFSDM1_CKOUT.X J5.20 ; port DFSDM1.CKOUT
PD4: J6.18 J6.20 PWDN.X ; port CAMERA.PWDN
PD5: JDIGITAL.23(18_TX1) ; port USART1.TX
PD6: JDIGITAL.24(19_RX1) ; port USART1.RX
PD7: J7.4 ; port SPI1.COPI
PD13: JDIGITAL.12(6) ; port PD13
PE4: JSIDE.30(49) ; port SAI1.FS_A
PE5: JSIDE.32(51) ; port SAI1.SCK_A
PE6: JSIDE.21(40) ; port LTDC.G1
PG7: JSIDE.34(53) ; port SAI1.MCLK_A
PG9: J7.1 ; port SPI1.CIPO
PG10: JSIDE.25(44) ; port LTDC.G3
PG11: DOUT3.X J6.13 ; port CAMERA.DOUT3
PG12: JSIDE.5(24) ; port LTDC.B1
PG13: JSIDE.4(23) ; port LTDC.R0
PG14: JDIGITAL.19(14_TX3) ; port USART3.TX
PH4: JDIGITAL.26(21_SCL) ; port I2C2.SCL
PH6: JDIGITAL.5(13) ; port SPI5.SCK
PH8: HREF.X J6.6 ; port CAMERA.HREF
PH9: DOUT0.X J6.16 ; port CAMERA.DOUT0
PH10: DOUT1.X J6.15 ; port CAMERA.DOUT1
PH11: DOUT2.X J6.14 ; port CAMERA.DOUT2
PH12: J6.4 JDIGITAL.2(SDA1) SDATA.X ; port CAMERA.SDATA, port I2C4.SDA  [project net I2C4.SDA]
PH13: JDIGITAL.21(16_TX2) ; port USART2.TX
PH14: DOUT4.X J6.12 ; port CAMERA.DOUT4
PH15: JSIDE.27(46) ; port LTDC.G4
PI0: I2S2_WS.X J5.14 ; port I2S2.WS
PI1: I2S2_CK.X J5.15 ; port I2S2.CK
PI2: IS2S_SDI.X J5.16 ; port I2S2.SDI
PI3: I2S2_SDO.X J5.17 ; port I2S2.SDO
PI4: DOUT5.X J6.11 ; port CAMERA.DOUT5
PI5: J6.5 VSYNC.X ; port CAMERA.VSYNC
PI6: DOUT6.X J6.10 ; port CAMERA.DOUT6
PI7: DOUT7.X J6.9 ; port CAMERA.DOUT7
PI9: JDIGITAL.22(17_RX2) ; port USART2.RX
PI10: JSIDE.24(43) ; port LTDC.HSYNC
PI11: JSIDE.31(50) ; port LTDC.G6
PI13: JSIDE.26(45) ; port LTDC.VSYNC
PI14: JSIDE.20(39) ; port LTDC.CLK
PI15: JSIDE.23(42) ; port LTDC.G2
PJ0: JSIDE.6(25) ; port LTDC.R1
PJ1: JSIDE.8(27) ; port LTDC.R2
PJ2: JSIDE.10(29) ; port LTDC.R3
PJ3: JSIDE.12(31) ; port LTDC.R4
PJ4: JSIDE.14(33) ; port LTDC.R5
PJ5: JSIDE.16(35) ; port LTDC.R6
PJ6: JSIDE.18(37) ; port LTDC.R7
PJ7: JSIDE.19(38) ; port LTDC.G0
PJ8: JDIGITAL.14(4) ; port PJ8
PJ9: J6.8 XCLK.X ; port CAMERA.XCLK
PJ10: JDIGITAL.7(11) ; port SPI5.COPI
PJ11: JDIGITAL.6(12) ; port SPI5.CIPO
PJ12: JSIDE.3(22) ; port LTDC.B0
PJ14: JSIDE.7(26) ; port LTDC.B2
PJ15: JSIDE.9(28) ; port LTDC.B3
PK0: JSIDE.29(48) ; port LTDC.G5
PK1: JDIGITAL.8(10) ; port SPI5.NSS
PK2: JSIDE.33(52) ; port LTDC.G7
PK3: JSIDE.11(30) ; port LTDC.B4
PK4: JSIDE.13(32) ; port LTDC.B5
PK5: JSIDE.15(34) ; port LTDC.B6
PK6: JSIDE.17(36) ; port LTDC.B7
PK7: JSIDE.22(41) ; port LTDC.DE
Net3V3_EN_X: J1.1 ; port ~{OFF}
NetJ1_3: J1.3 ; port VRTC
NetJDIGITAL_3: JDIGITAL.3(AREF) ; port AREF

Not connected (* = marked no-connect by the designer): J8 6* 7* 8*; JANALOG 1(NC)*

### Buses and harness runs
harness I2C4 = port I2C4

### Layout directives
net class LTDC: PE6, PG10, PG12, PG13, PH15, PI10, PI11, PI13, PI14, PI15, PJ0, PJ1, PJ2, PJ3, PJ4, PJ5, PJ6, PJ7, PJ12, PJ14, PJ15, PK0, PK2, PK3, PK4, PK5, PK6, PK7

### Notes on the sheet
- CAMERA SHARES:
  I2C4 WITH JDIGITAL
- B0
- B1
- B2
- B3
- B4
- R0
- R1
- R2
- R3
- R4
- B5
- B6
- B7
- G0
- G1
- R5
- R6
- R7
- CLK
- DE
- J6
- J5
- G2
- G3
- G4
- G5
- G6
- HSYNC
- VSYNC
- G7
- JSIDE
- JDIGITAL SHARES:
  I2C4 WITH CAMERA AND CRYPTOCHIP
- J1
- CIPO
- SCK
- COPI
- J7
- J8
- JANALOG
- JDIGITAL
- H7: USART1/LPUART1
- H7: USART6
- H7: USART4
- H7: USART2

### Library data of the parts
3V3_J5 5V_J5 DFSDM1_CKOUT DFSDM1_DATIN0 DOUT0-DOUT7 DSI_CK_N DSI_CK_P DSI_D0_P DSI_D1_N DSI_D1_P DSID0N GND_J5 HREF I2S2_CK I2S2_MCK I2S2_SDO I2S2_WS IS2S_SDI JTAG_3V3 JTAG_GND JTAG_NRST JTAG_TCK_SCK JTAG_TMS/SWD PB12 PCLK POWER_EN PWDN SCL4 SDATA VSYNC XCLK = UT0013-A.4: Test point 1.00mm
J1 = J0237-A.2: MOUNT A MALE HEADER TH 2.54mm VERT. 1x003POS; Code Arduino: J0237
J5 = J0265-A.9: CONN SOCKET 2ROW 24POS VERTICAL PASS THROUGH + SMD with fixing + reel + cap for pick and place; Manufacturer: 4UCON; Connector Type: BOARD CONNECTOR; Code Arduino: J0265; Number of Contacts: 24
J6 = J0249-A.9: CONN SOCKET 2ROW 20POS VERTICAL PASS THROUGH + SMD with fixing + pick and place cap, in reel; Manufacturer: 4UCON; Connector Type: BOARD CONNECTOR; Code Arduino: J0249; Number of Contacts: 20
J7 = J0004-A.5: CONN Header Through Hole 6 position 0.100" (2.54mm); Manufacturer: Adam Tech; Code Arduino: 0114
J8 = J0089-A.11: CONN HEADER SMD 10POS 2x5 1.27MM JTAG reel, capsfor pick and place; Manufacturer: 4UCON; Code Arduino: J0089; Gender: Male; Current Rating: 1.75A; Connector Type: Male Pin
JANALOG = J0313-A.5: CONN THD 24X1 CUSTOM PITCH DUE JANALOG GREY; Manufacturer: 4UCON; Number of Contacts: 24; Code Arduino: 3654
JDIGITAL = J0262-A.10: CONN THD 1X26 CUSTOM PITCH DUE JDIGITAL GREY; Manufacturer: 4UCON; Code Arduino: 3653; Number of Positions: 26
JSIDE = J0315-A.4: CONN THD 18X2 36V DUE JSIDE CUSTOM GREY; Manufacturer: 4UCON; Number of Contacts: 36; Code Arduino: 3656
